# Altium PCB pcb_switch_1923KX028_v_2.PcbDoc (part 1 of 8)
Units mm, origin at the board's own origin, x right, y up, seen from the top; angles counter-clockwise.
Board outline 297.2 x 112.05 mm, 6 copper layers (Component Side, GND Layer 1, Inner Layer 1, Inner Layer 2, GND Layer 2, Solder Side), stack 1.578 mm thick; 545 components, 377 nets, 3174 pads, 1537 vias.
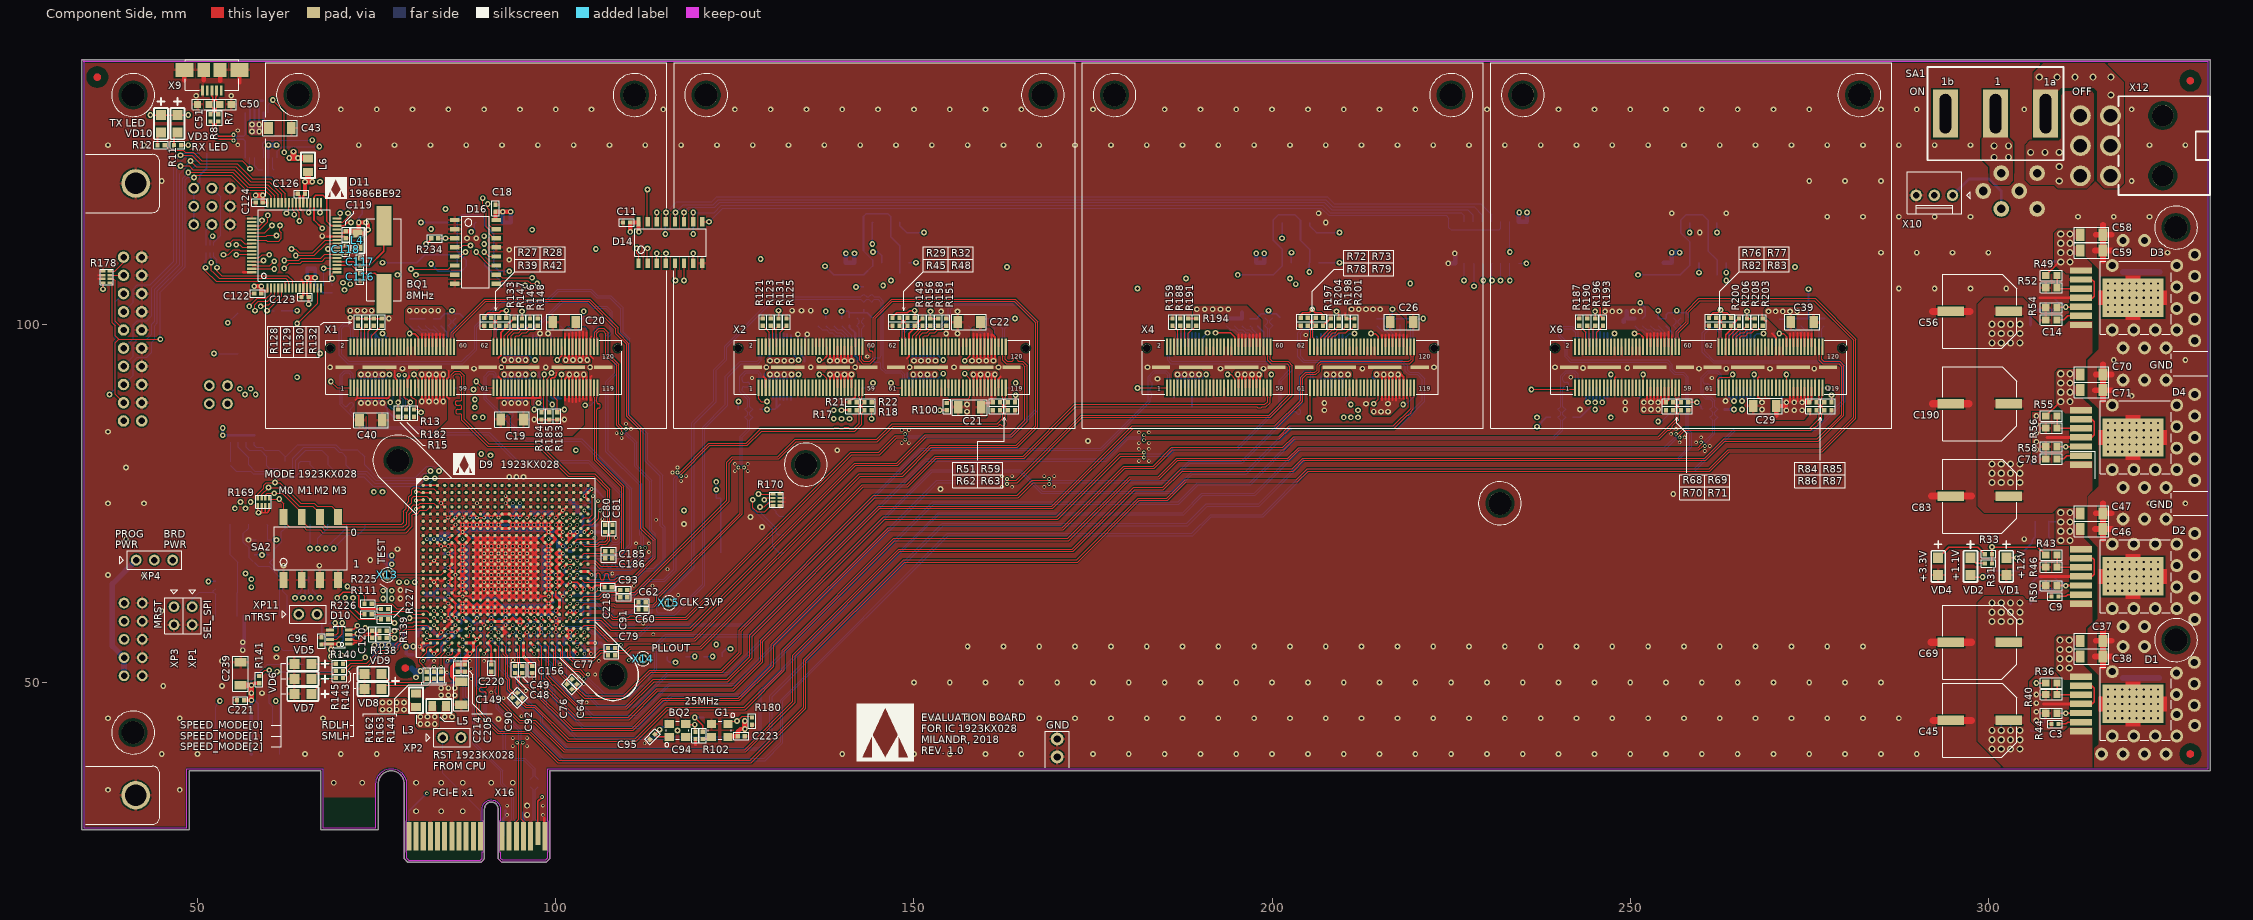
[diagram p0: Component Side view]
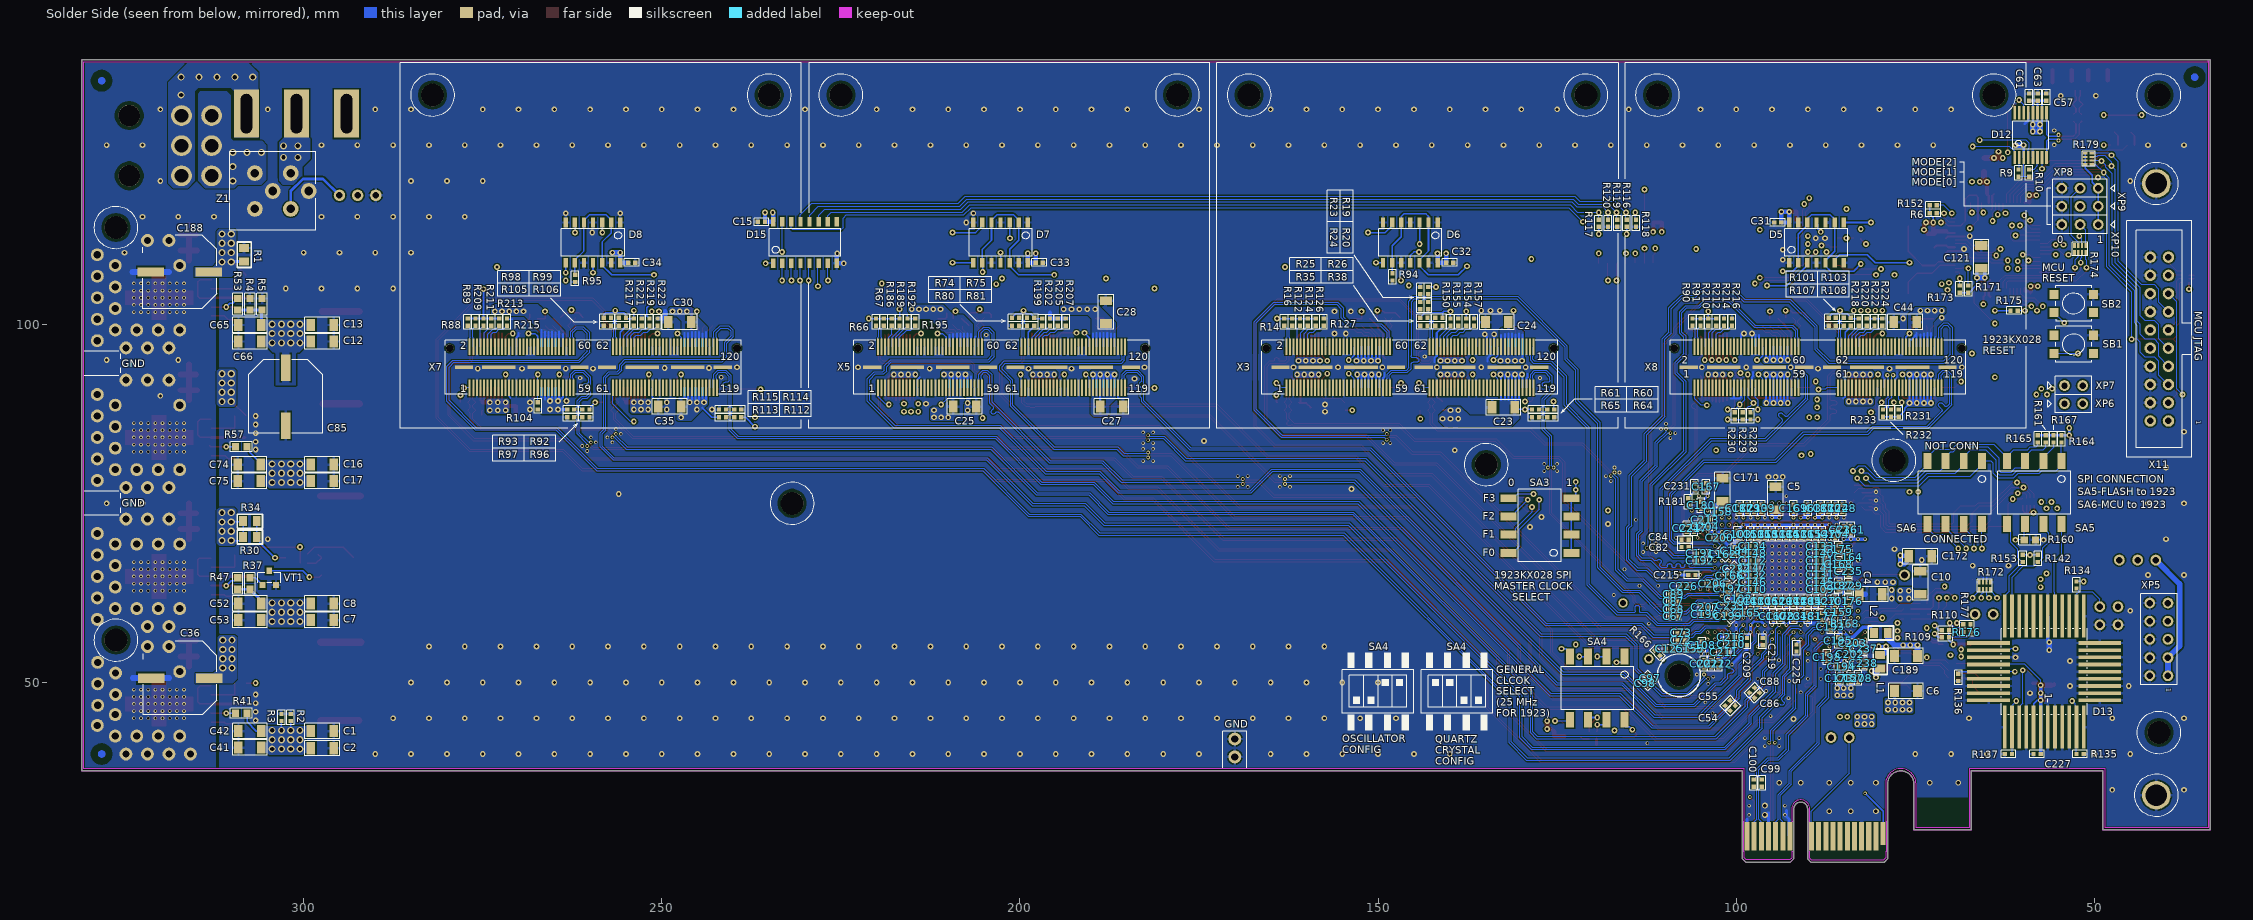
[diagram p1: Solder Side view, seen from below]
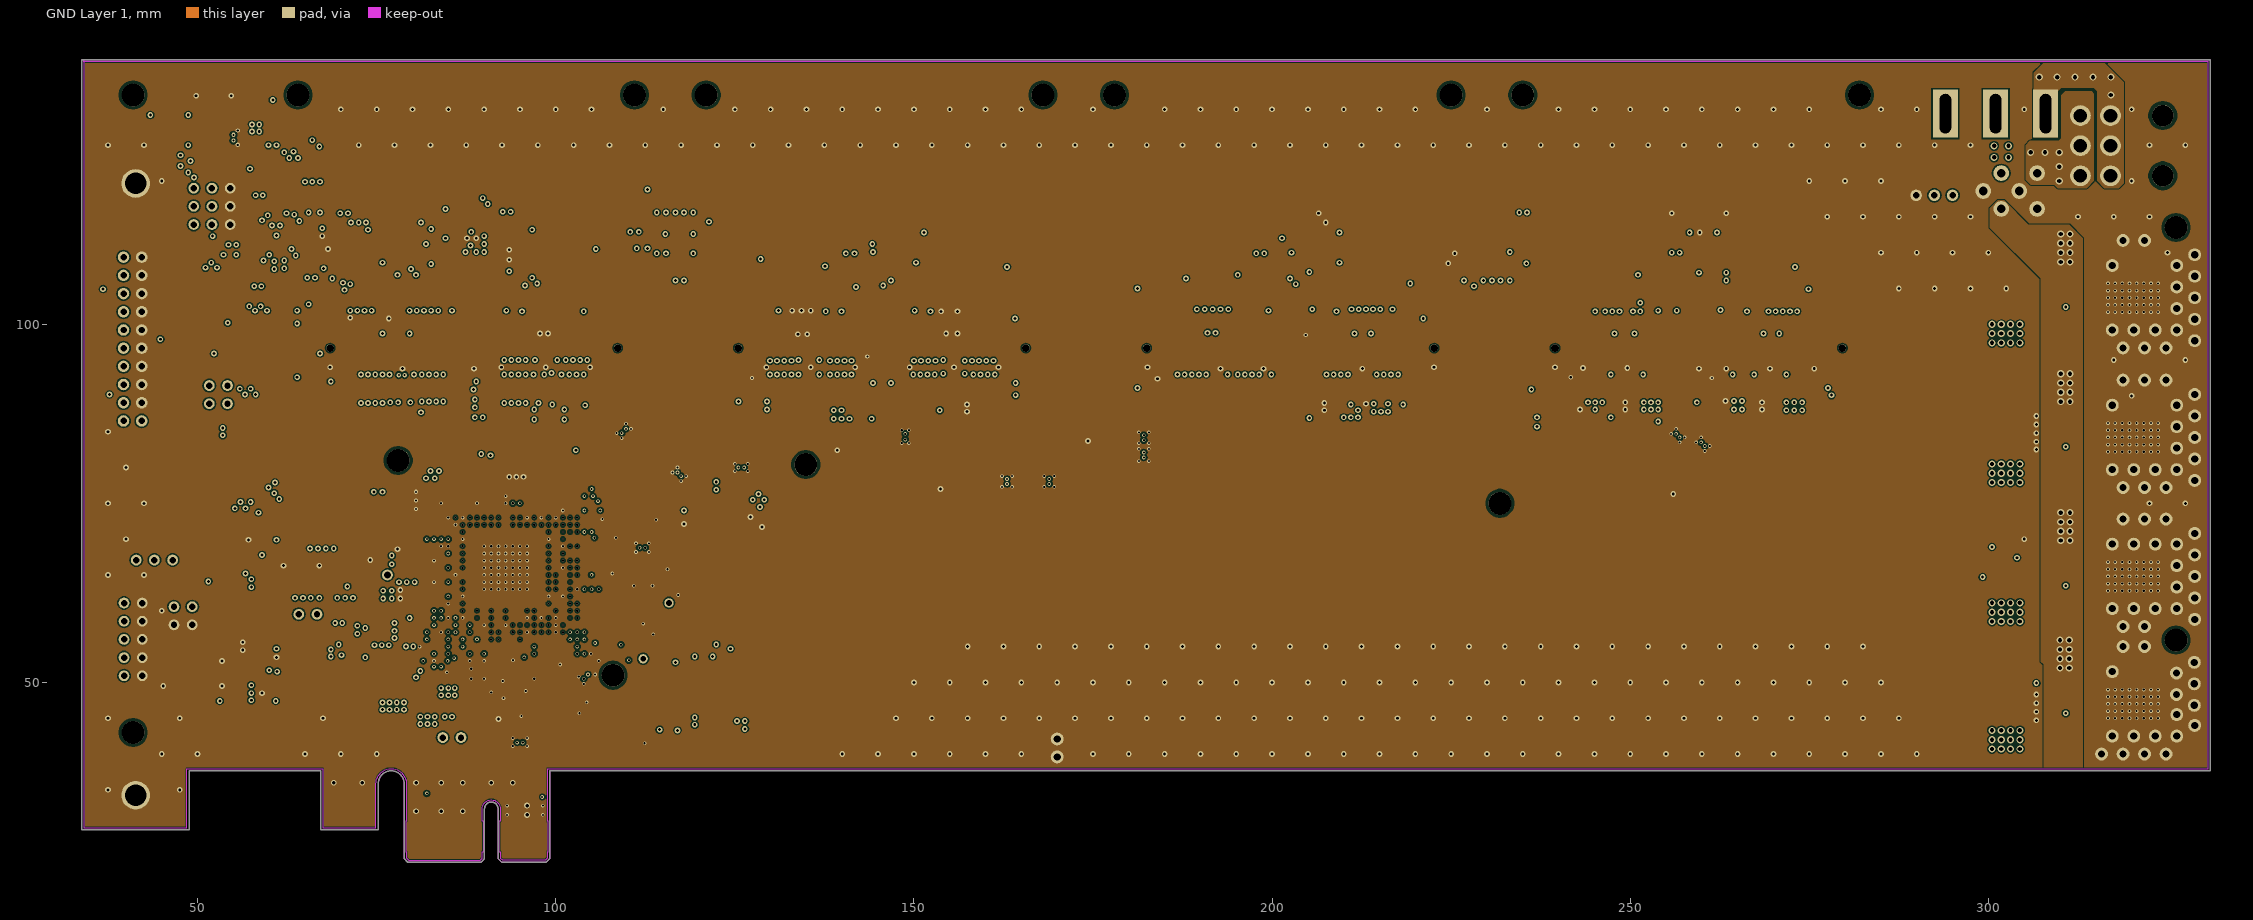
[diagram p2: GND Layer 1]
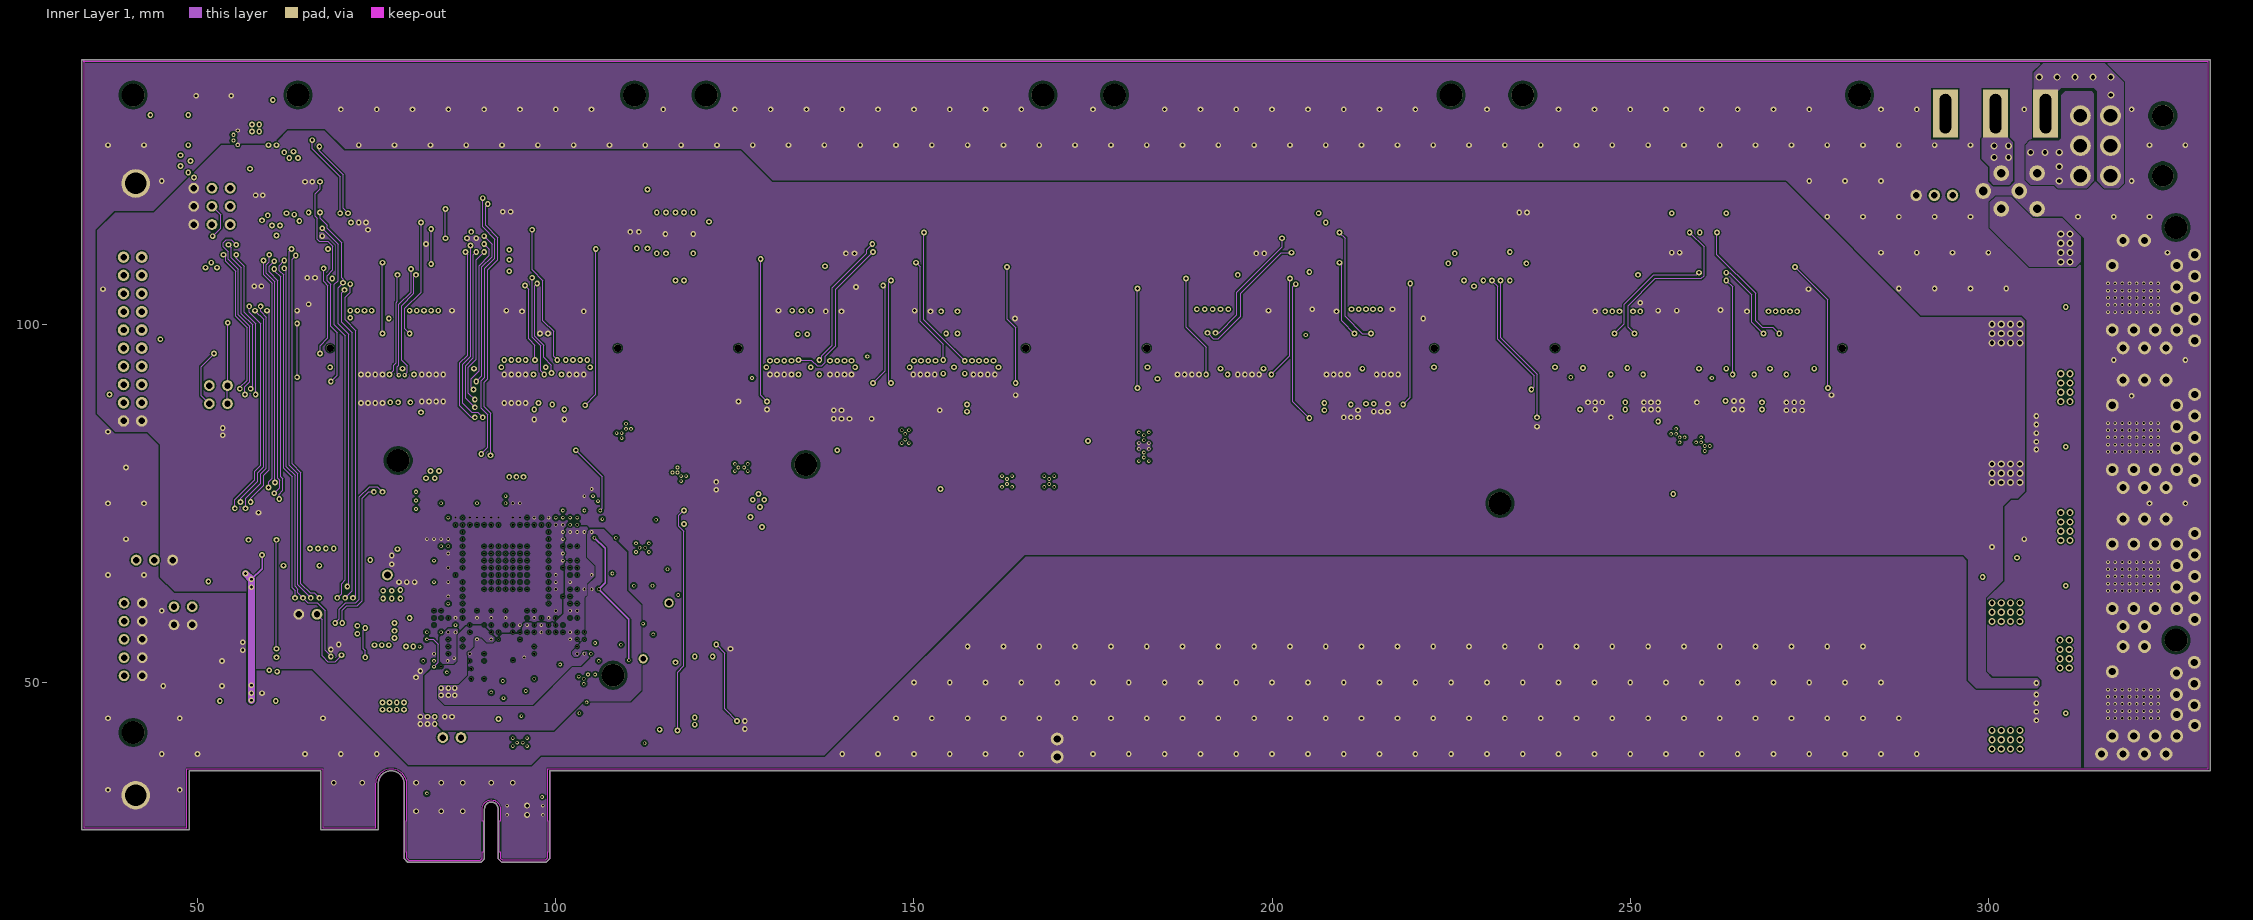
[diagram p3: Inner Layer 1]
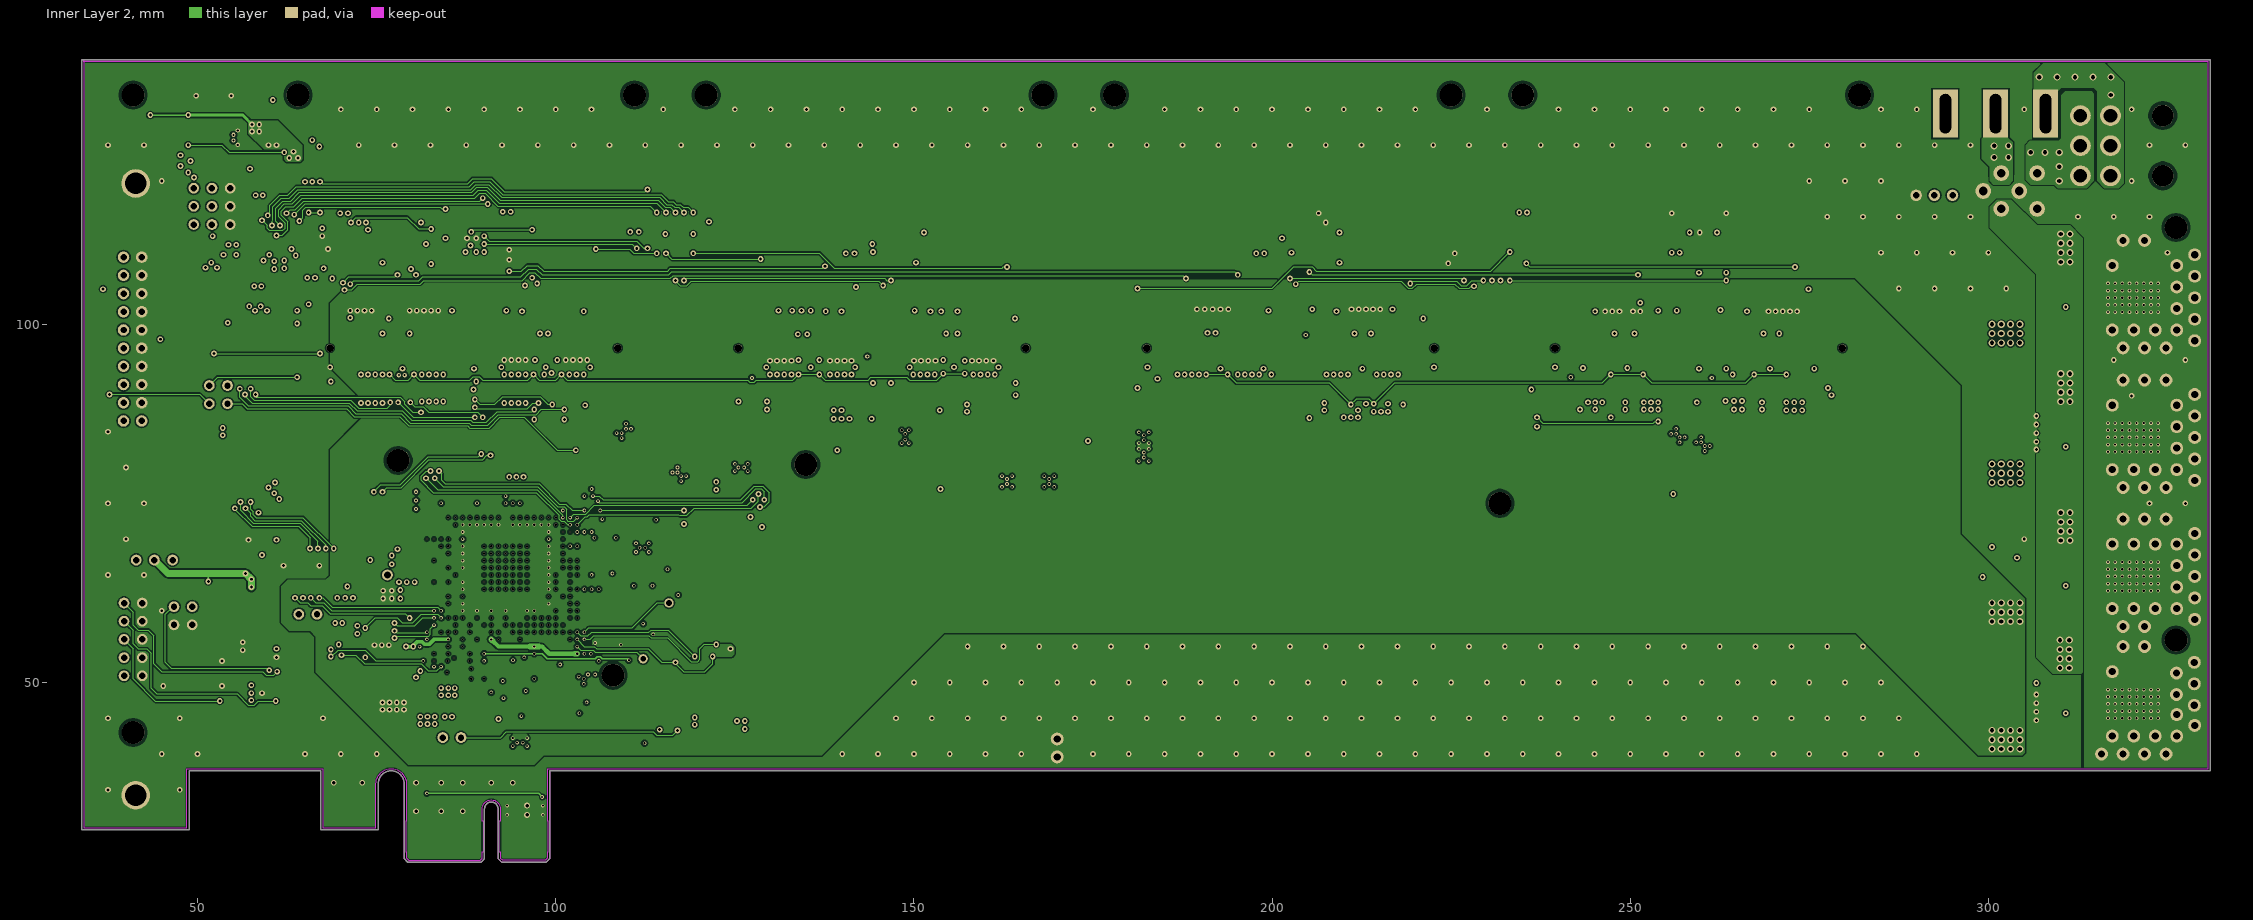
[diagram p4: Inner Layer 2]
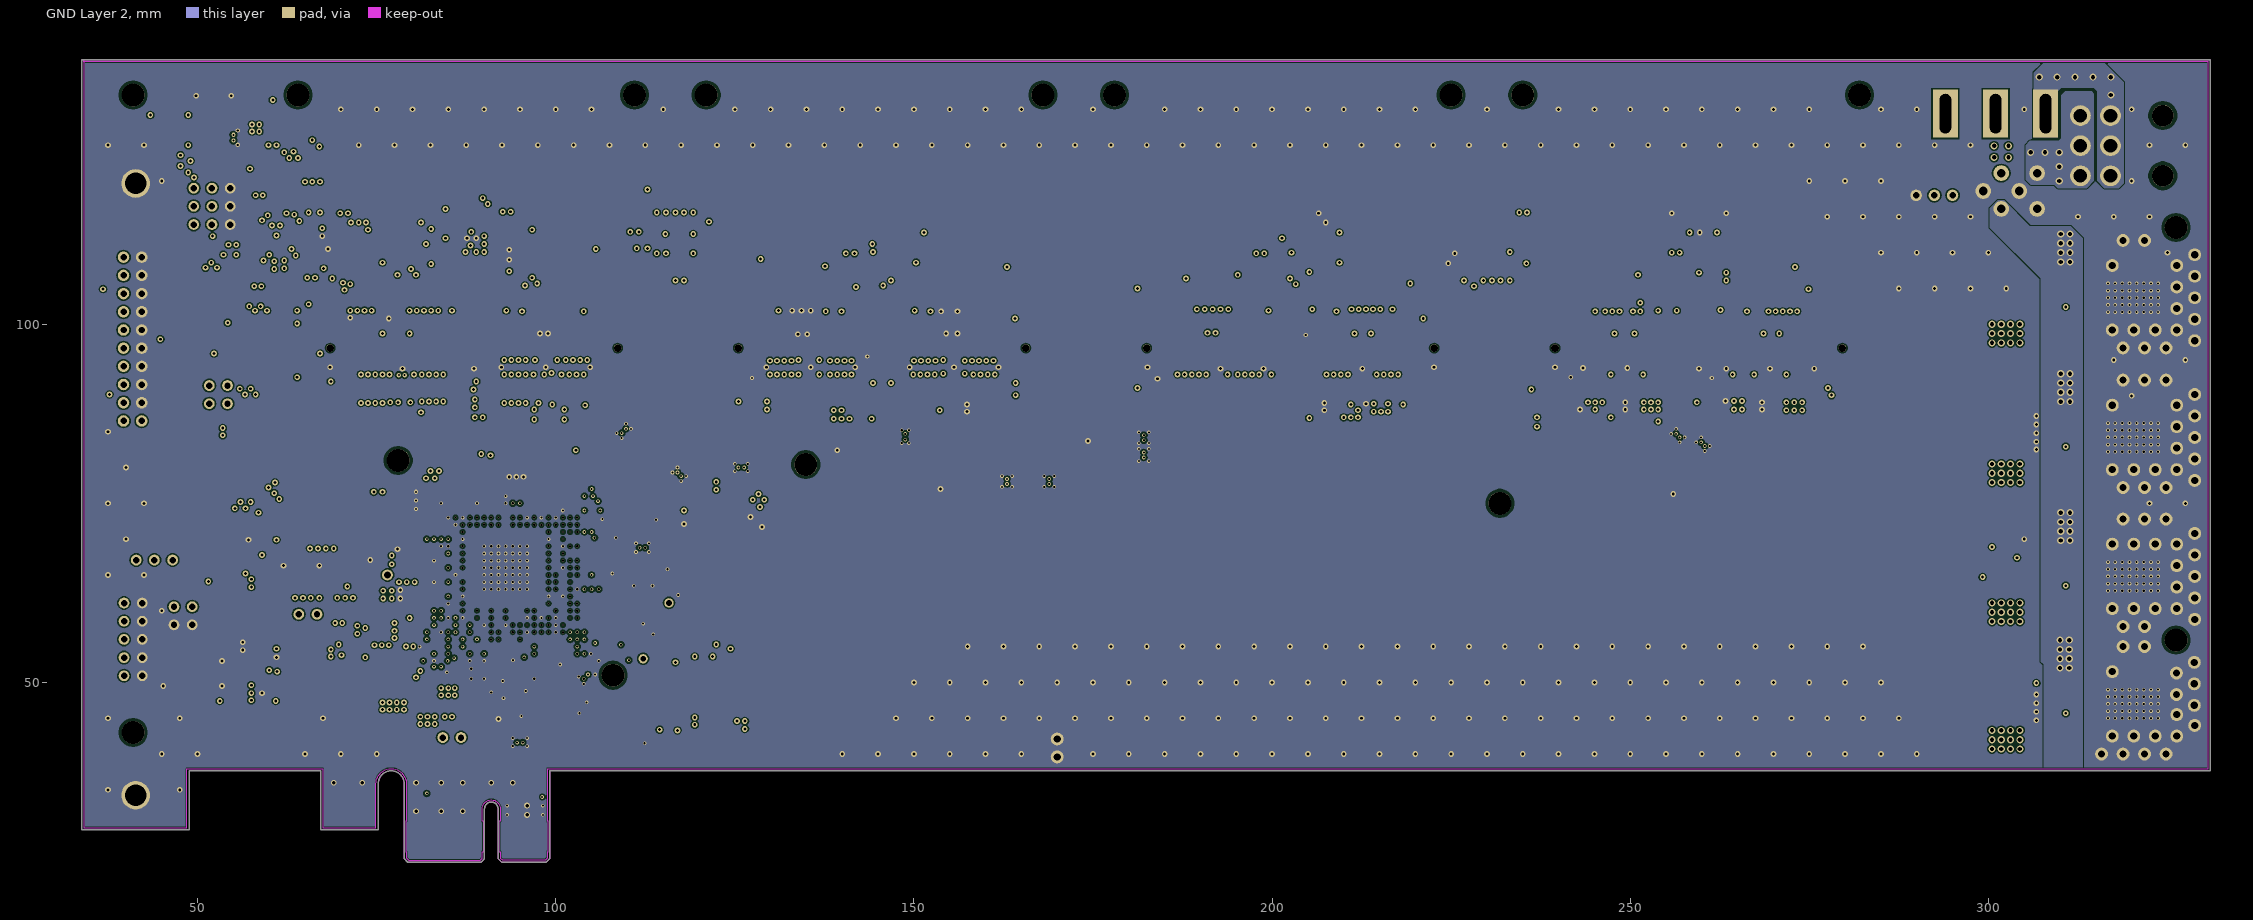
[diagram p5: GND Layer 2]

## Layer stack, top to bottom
Top Solder: solder mask 0.0102, Solder Resist, Dk 3.5
Component Side: signal copper 0.018
Dielectric 1: prepreg 0.15, Prepreg_1080, Dk 4.2
GND Layer 1: signal copper 0.018
Dielectric 3: core 0.51, FR-4, Dk 4.7
Inner Layer 1: signal copper 0.018
Dielectric 6: prepreg 0.15, Prepreg_1080, Dk 4.2
Inner Layer 2: signal copper 0.018
Dielectric 5: core 0.51, FR-4, Dk 4.7
GND Layer 2: signal copper 0.018
Dielectric 4: prepreg 0.15, Prepreg_1080, Dk 4.2
Solder Side: signal copper 0.018
Bottom Solder: solder mask 0.0102, Solder Resist, Dk 3.5

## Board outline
48.8,29.4 48.8,37.65 67.2,37.65 67.2,29.4 75.2,29.4 75.2,35.825 cw(c77.025,35.825) 78.85,35.825 78.85,25.4 79.35,24.9 89.575,24.9 90.05,25.375 90.05,32.35 cw(c91,32.35) 91.95,32.35 91.95,25.4 92.425,24.925 98.675,24.925 99.15,25.4 99.15,37.65 331,37.65 331,136.95 33.8,136.95 33.8,29.4
cut-out: 33.8,136.95 34.1,136.95 34.1,29.7 48.5,29.7 48.5,37.95 67.5,37.95 67.5,29.7 74.9,29.7 74.9,35.825 cw(c77.025,35.825) 79.15,35.825 79.15,30.625 79.025,30.625 79.025,26.375 79.15,26.375 79.15,25.5 79.45,25.2 89.475,25.2 89.75,25.475 89.75,26.375 89.975,26.375 89.975,30.625 89.75,30.625 89.75,32.35 cw(c91,32.35) 92.25,32.35 92.25,30.625 92.025,30.625 92.025,26.375 92.25,26.375 92.25,25.475 92.5,25.225 98.575,25.225 98.85,25.5 98.85,26.375 98.975,26.375 98.975,30.625 98.85,30.625 98.85,37.95 330.7,37.95 330.7,136.65 34.1,136.65 34.1,136.95 331,136.95 331,37.65 99.15,37.65 99.15,25.4 98.675,24.925 92.425,24.925 91.95,25.4 91.95,32.35 ccw(c91,32.35) 90.05,32.35 90.05,25.375 89.575,24.9 79.35,24.9 78.85,25.4 78.85,35.825 ccw(c77.025,35.825) 75.2,35.825 75.2,29.4 67.2,29.4 67.2,37.65 48.8,37.65 48.8,29.4 33.8,29.4

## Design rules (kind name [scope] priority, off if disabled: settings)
Clearance Clearance_On_Internal_LAYER_2_vs_VIA [OnLayer('Inner Layer 2') vs IsVia] p1 off: gap=0.125 except(0.15: Arc-Via Track-Via SMDPad-Via; 0.2: Arc-Poly Track-Poly SMDPad-Fill SMDPad-Poly THPad-Via THPad-Poly Via-Via Fill-Poly Poly-Poly Poly-Region Poly-Text; 0.25: Track-THPad Via-Poly; 0.35: Arc-THPad SMDPad-THPad THPad-THPad THPad-Fill THPad-Region THPad-Text Via-Fill Via-Region Via-Text)
Clearance Clearance_On_Internal_Layer_1_vs_VIA [OnLayer('Inner Layer 1') vs IsVia] p2 off: gap=0.125 except(0.15: Arc-Via Track-Via SMDPad-Via; 0.2: Arc-Poly Track-Poly SMDPad-Fill SMDPad-Poly THPad-Via Via-Via Fill-Poly Poly-Poly Poly-Region Poly-Text; 0.25: Track-THPad THPad-Poly Via-Poly; 0.35: Arc-THPad SMDPad-THPad THPad-THPad THPad-Fill THPad-Region THPad-Text Via-Fill Via-Region Via-Text)
Clearance Clearance_On_BOTTOM_LAYER_vs_VIA [OnLayer('Solder Side') vs IsVia] p3 off: gap=0.125 except(0.15: Arc-Via Track-Via SMDPad-Via; 0.2: Arc-Poly Track-Poly SMDPad-Fill SMDPad-Poly THPad-Via THPad-Poly Via-Via Via-Poly Fill-Poly Poly-Poly Poly-Region Poly-Text; 0.25: Track-THPad; 0.35: Arc-THPad SMDPad-THPad THPad-THPad THPad-Fill THPad-Region THPad-Text Via-Fill Via-Region Via-Text)
Clearance Clearance_On_TOP_LAYER_vs_VIA [OnLayer('Component Side') vs isVia] p4 off: gap=0.125 except(0.15: Arc-Via Track-Via SMDPad-Via; 0.2: Arc-Poly Track-Poly SMDPad-Fill SMDPad-Poly THPad-Via THPad-Poly Via-Via Via-Poly Fill-Poly Poly-Poly Poly-Region Poly-Text; 0.25: Track-THPad; 0.35: Arc-THPad SMDPad-THPad THPad-THPad THPad-Fill THPad-Region THPad-Text Via-Fill Via-Region Via-Text)
Clearance Clearance_Int_layer_1_vs_VIA_without_an_ring [HoleDiameter < 0.4 vs OnLayer('Inner Layer 1')] p5: gap=0.125 except(0.15: Arc-Via Track-Via SMDPad-Via; 0.2: Arc-Poly Track-Poly SMDPad-Fill SMDPad-Poly THPad-Via THPad-Poly Via-Via Fill-Poly Poly-Poly Poly-Region Poly-Text; 0.25: Track-THPad Via-Fill Via-Poly Via-Region; 0.35: Arc-THPad SMDPad-THPad THPad-THPad THPad-Fill THPad-Region THPad-Text Via-Text)
Clearance Clearance_Int_layer_2_vs_VIA_without_an_ring [HoleDiameter < 0.4 vs OnLayer('Inner Layer 2')] p6: gap=0.125 except(0.15: Arc-Via Track-Via SMDPad-Via; 0.2: Arc-Poly Track-Poly SMDPad-Fill SMDPad-Poly THPad-Via THPad-Poly Via-Via Fill-Poly Poly-Poly Poly-Region Poly-Text; 0.25: Track-THPad Via-Fill Via-Poly Via-Region; 0.35: Arc-THPad SMDPad-THPad THPad-THPad THPad-Fill THPad-Region THPad-Text Via-Text)
Clearance Clearance_Int_layer_3_vs_VIA_without_an_ring_1 [HoleDiameter < 0.4 vs OnLayer('GND Layer 1')] p7: gap=0.125 except(0.15: Arc-Via Track-Via SMDPad-Via; 0.2: Arc-Poly Track-Poly SMDPad-Fill SMDPad-Poly THPad-Via THPad-Poly Via-Via Fill-Poly Poly-Poly Poly-Region Poly-Text; 0.25: Track-THPad Via-Fill Via-Poly Via-Region; 0.35: Arc-THPad SMDPad-THPad THPad-THPad THPad-Fill THPad-Region THPad-Text Via-Text)
Clearance Clearance_Int_layer_4_vs_VIA_without_an_ring [HoleDiameter < 0.4 vs OnLayer('GND Layer 2')] p8: gap=0.125 except(0.15: Arc-Via Track-Via SMDPad-Via; 0.2: Arc-Poly Track-Poly SMDPad-Fill SMDPad-Poly THPad-Via THPad-Poly Via-Via Fill-Poly Poly-Poly Poly-Region Poly-Text; 0.25: Track-THPad Via-Fill Via-Poly Via-Region; 0.35: Arc-THPad SMDPad-THPad THPad-THPad THPad-Fill THPad-Region THPad-Text Via-Text)
Clearance [All] p9: gap=0.125 except(0.15: Arc-Via Track-Via SMDPad-Via; 0.17: Via-Poly; 0.2: Arc-Poly Track-Poly SMDPad-Fill SMDPad-Poly THPad-Via THPad-Poly Via-Via Fill-Poly Poly-Poly Poly-Region Poly-Text; 0.25: Track-THPad; 0.35: Arc-THPad SMDPad-THPad THPad-THPad THPad-Fill THPad-Region THPad-Text Via-Fill Via-Region Via-Text)
ComponentClearance [All] p1 off: gap=0.01 collisioncheckmode=3 verticalgap=0.01 showdistances=FALSE
ComponentOrientations [All] p1: allowedrotations=32
DiffPairsRouting "Schematic Differential Pairs Routing_3" [InNet('USB_D_P')] p1: maxlimit=0.3 minlimit=0.125 mostfreqgap=0.254 toplayer_prefgap=0.21 toplayer_minwidth=0.125 toplayer_maxwidth=0.3 toplayer_prefwidth=0.22 midlayer1_mingap=0.254 midlayer1_maxgap=0.254 midlayer1_minwidth=0.381 midlayer1_maxwidth=0.381 midlayer1_prefwidth=0.381 midlayer2_mingap=0.254 midlayer2_maxgap=0.254 midlayer2_minwidth=0.381 midlayer2_maxwidth=0.381 midlayer2_prefwidth=0.381 midlayer3_mingap=0.254 midlayer3_maxgap=0.254 midlayer3_minwidth=0.381 midlayer3_maxwidth=0.381 midlayer3_prefwidth=0.381 midlayer4_mingap=0.254 midlayer4_maxgap=0.254 midlayer4_minwidth=0.381 midlayer4_maxwidth=0.381 midlayer4_prefwidth=0.381 bottomlayer_prefgap=0.21 bottomlayer_minwidth=0.125 bottomlayer_maxwidth=0.3 bottomlayer_prefwidth=0.22 maxuncoupledlength=12.7
DiffPairsRouting "Schematic Differential Pairs Routing_2" [InNet('USB_D_N')] p2: maxlimit=0.3 minlimit=0.125 mostfreqgap=0.254 toplayer_prefgap=0.21 toplayer_minwidth=0.125 toplayer_maxwidth=0.3 toplayer_prefwidth=0.22 midlayer1_mingap=0.254 midlayer1_maxgap=0.254 midlayer1_minwidth=0.381 midlayer1_maxwidth=0.381 midlayer1_prefwidth=0.381 midlayer2_mingap=0.254 midlayer2_maxgap=0.254 midlayer2_minwidth=0.381 midlayer2_maxwidth=0.381 midlayer2_prefwidth=0.381 midlayer3_mingap=0.254 midlayer3_maxgap=0.254 midlayer3_minwidth=0.381 midlayer3_maxwidth=0.381 midlayer3_prefwidth=0.381 midlayer4_mingap=0.254 midlayer4_maxgap=0.254 midlayer4_minwidth=0.381 midlayer4_maxwidth=0.381 midlayer4_prefwidth=0.381 bottomlayer_prefgap=0.21 bottomlayer_minwidth=0.125 bottomlayer_maxwidth=0.3 bottomlayer_prefwidth=0.22 maxuncoupledlength=12.7
DiffPairsRouting "Schematic Differential Pairs Routing_1" [InNet('_USB_D_P')] p3: maxlimit=0.3 minlimit=0.125 mostfreqgap=0.254 toplayer_prefgap=0.21 toplayer_minwidth=0.125 toplayer_maxwidth=0.3 toplayer_prefwidth=0.22 midlayer1_mingap=0.254 midlayer1_maxgap=0.254 midlayer1_minwidth=0.381 midlayer1_maxwidth=0.381 midlayer1_prefwidth=0.381 midlayer2_mingap=0.254 midlayer2_maxgap=0.254 midlayer2_minwidth=0.381 midlayer2_maxwidth=0.381 midlayer2_prefwidth=0.381 midlayer3_mingap=0.254 midlayer3_maxgap=0.254 midlayer3_minwidth=0.381 midlayer3_maxwidth=0.381 midlayer3_prefwidth=0.381 midlayer4_mingap=0.254 midlayer4_maxgap=0.254 midlayer4_minwidth=0.381 midlayer4_maxwidth=0.381 midlayer4_prefwidth=0.381 bottomlayer_prefgap=0.21 bottomlayer_minwidth=0.125 bottomlayer_maxwidth=0.3 bottomlayer_prefwidth=0.22 maxuncoupledlength=12.7
DiffPairsRouting "Schematic Differential Pairs Routing" [InNet('_USB_D_N')] p4: maxlimit=0.3 minlimit=0.125 mostfreqgap=0.254 toplayer_prefgap=0.21 toplayer_minwidth=0.125 toplayer_maxwidth=0.3 toplayer_prefwidth=0.22 midlayer1_mingap=0.254 midlayer1_maxgap=0.254 midlayer1_minwidth=0.381 midlayer1_maxwidth=0.381 midlayer1_prefwidth=0.381 midlayer2_mingap=0.254 midlayer2_maxgap=0.254 midlayer2_minwidth=0.381 midlayer2_maxwidth=0.381 midlayer2_prefwidth=0.381 midlayer3_mingap=0.254 midlayer3_maxgap=0.254 midlayer3_minwidth=0.381 midlayer3_maxwidth=0.381 midlayer3_prefwidth=0.381 midlayer4_mingap=0.254 midlayer4_maxgap=0.254 midlayer4_minwidth=0.381 midlayer4_maxwidth=0.381 midlayer4_prefwidth=0.381 bottomlayer_prefgap=0.21 bottomlayer_minwidth=0.125 bottomlayer_maxwidth=0.3 bottomlayer_prefwidth=0.22 maxuncoupledlength=12.7
DiffPairsRouting DiffPairsRouting_1 [InDifferentialPairClass('All Differential Pairs')] p5: maxlimit=0.3 minlimit=0.125 mostfreqgap=0.3 toplayer_maxgap=0.2 toplayer_prefgap=0.16 toplayer_minwidth=0.125 toplayer_maxwidth=0.22 toplayer_prefwidth=0.15 midlayer1_minwidth=0.125 midlayer1_maxwidth=0.22 midlayer1_prefwidth=0.15 midlayer2_minwidth=0.125 midlayer2_maxwidth=0.22 midlayer2_prefwidth=0.15 midlayer3_mingap=0.254 midlayer3_maxgap=0.2 midlayer3_prefgap=0.254 midlayer3_minwidth=0.381 midlayer3_maxwidth=0.22 midlayer3_prefwidth=0.381 midlayer4_mingap=0.254 midlayer4_maxgap=0.2 midlayer4_prefgap=0.254 midlayer4_minwidth=0.381 midlayer4_maxwidth=0.22 midlayer4_prefwidth=0.381 bottomlayer_maxgap=0.2 bottomlayer_prefgap=0.16 bottomlayer_minwidth=0.125 bottomlayer_maxwidth=0.22 bottomlayer_prefwidth=0.15 maxuncoupledlength=20
Height [All] p1 off: minheight=0 maxheight=50 prefheight=25
HoleSize [All] p1: absolutevalues=TRUE maxlimit=6 minlimit=0.3 maxpercent=80.000 minpercent=20.000
HoleToHoleClearance [All] p1: gap=0.2 allowstackedmicrovias=FALSE
MinimumSolderMaskSliver [All] p1: minsoldermaskwidth=0.01
PlaneClearance [All] p1: clearance=0.35
PlaneConnect PlaneConnect_2 [InNet('+12') Or InNet('NetXP3_4')] p1 off: planeconnectstyle=Direct reliefexpansion=0.508 reliefentries=4 reliefconductorwidth=0.254 reliefairgap=0.254
PlaneConnect [IsVia] p2: planeconnectstyle=Direct reliefexpansion=0.508 reliefentries=4 reliefconductorwidth=0.254 reliefairgap=0.254
PlaneConnect PlaneConnect_1 [All] p3: planeconnectstyle=Relief reliefexpansion=0.1 reliefentries=4 reliefconductorwidth=0.2 reliefairgap=0.2
PolygonConnect connection_poly_by_name [All vs IsNamedPolygon('TL_USB_3.3V') Or IsNamedPolygon('IL2_USB_3.3V') Or IsNamedPolygon('IL2_NetSA1_2') Or IsNamedPolygon('TL_NetXP3_4') Or IsNamedPolygon('IL2_12V') Or IsNamedPolygon('CS_GND_DIRECT_CONN') Or IsNamedPolygon('TL_DIRTY_GND') Or IsNamedPolygon('TL_1.1V') Or IsNamedPolygon('TL_3.3V') or IsNamedPolygon('TL_NET_FIL_3.3V') or IsNamedPolygon('TL_D9_1.1V') Or IsNamedPolygon('TL_D9_1.1V_PCIE') Or IsNamedPolygon('ALL_+1.1') Or IsNamedPolygon('ALL_+3.3') Or IsNamedPolygon('Inner_Layer_1_INPUTPWR') oR IsNamedPolygon('IL1_GND') Or IsNamedPolygon('BL_1.1_X5') or IsNamedPolygon('TL_GND_X') Or IsNamedPolygon('BL_3.3_X3') Or IsNamedPolygon('INT_LAYER_GND')] p1: connectstyle=Direct reliefconductorwidth=0.254 reliefentries=4 polygonreliefangle="90 Angle" airgapwidth=0.254
PolygonConnect connection_via [IsVia] p2: connectstyle=Direct reliefconductorwidth=0.254 reliefentries=4 polygonreliefangle="90 Angle" airgapwidth=0.254
PolygonConnect connection_QSH_central_pads [HasFootprint('QSH-60-01-F-D-A')] p3: connectstyle=Relief reliefconductorwidth=0.28 reliefentries=4 polygonreliefangle="90 Angle" airgapwidth=0.2
PolygonConnect connection_1923 [HasFootprint('FOOTPRINT_MK8303.576-1')] p4: connectstyle=Relief reliefconductorwidth=0.2 reliefentries=4 polygonreliefangle="45 Angle" airgapwidth=0.2
PolygonConnect connection_all [All] p5: connectstyle=Relief reliefconductorwidth=0.4 reliefentries=4 polygonreliefangle="90 Angle" airgapwidth=0.2
RoutingCorners RoutingCorners_1 [All] p1: cornerstyle=45-Degree minsetback=2.54 maxsetback=2.54
RoutingLayers RoutingLayers_1 [All] p1: top layer_v5=TRUE mid layer 1_v5=TRUE mid layer 2_v5=TRUE mid layer 3_v5=TRUE mid layer 4_v5=TRUE bottom layer_v5=TRUE
RoutingLayers RoutingLayers_for_Diff [InDifferentialPairClass('All Differential Pairs')] p2 off: top layer_v5=FALSE mid layer 1_v5=FALSE mid layer 2_v5=FALSE mid layer 3_v5=TRUE mid layer 4_v5=TRUE bottom layer_v5=FALSE
RoutingVias [All] p1: holewidth=0.3 width=0.5 viastyle="Through Hole" minholewidth=0.3 minwidth=0.3 maxholewidth=0.6 maxwidth=1
SilkToSilkClearance [All] p1: silktosilkclearance=0.01
SilkToSolderMaskClearance [IsPad] p1: minsilkscreentomaskgap=0.01 clearancetoexposedcopper=TRUE
SolderMaskExpansion [All] p1: expansion=0.05
Width [All] p1: maxlimit=1 minlimit=0.125 preferedwidth=0.15
18 further rules are at their usual default settings.

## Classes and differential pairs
differential pair USB_D: +USB_D_P -USB_D_N
differential pair SGMII_L3DATO_3: +SGMII_L3DATO_3_P -SGMII_L3DATO_3_N
differential pair SGMII_L3DATO_2: +SGMII_L3DATO_2_P -SGMII_L3DATO_2_N
differential pair SGMII_L3DATO_1: +SGMII_L3DATO_1_P -SGMII_L3DATO_1_N
differential pair SGMII_L3DATO_0: +SGMII_L3DATO_0_P -SGMII_L3DATO_0_N
differential pair SGMII_L3DATI_3: +SGMII_L3DATI_3_P -SGMII_L3DATI_3_N
differential pair SGMII_L3DATI_2: +SGMII_L3DATI_2_P -SGMII_L3DATI_2_N
differential pair SGMII_L3DATI_1: +SGMII_L3DATI_1_P -SGMII_L3DATI_1_N
differential pair SGMII_L3DATI_0: +SGMII_L3DATI_0_P -SGMII_L3DATI_0_N
differential pair SGMII_L2DATO_3: +SGMII_L2DATO_3_P -SGMII_L2DATO_3_N
differential pair SGMII_L2DATO_2: +SGMII_L2DATO_2_P -SGMII_L2DATO_2_N
differential pair SGMII_L2DATO_1: +SGMII_L2DATO_1_P -SGMII_L2DATO_1_N
differential pair SGMII_L2DATO_0: +SGMII_L2DATO_0_P -SGMII_L2DATO_0_N
differential pair SGMII_L2DATI_3: +SGMII_L2DATI_3_P -SGMII_L2DATI_3_N
differential pair SGMII_L2DATI_2: +SGMII_L2DATI_2_P -SGMII_L2DATI_2_N
differential pair SGMII_L2DATI_1: +SGMII_L2DATI_1_P -SGMII_L2DATI_1_N
differential pair SGMII_L2DATI_0: +SGMII_L2DATI_0_P -SGMII_L2DATI_0_N
differential pair SGMII_L1DATO_3: +SGMII_L1DATO_3_P -SGMII_L1DATO_3_N
differential pair SGMII_L1DATO_2: +SGMII_L1DATO_2_P -SGMII_L1DATO_2_N
differential pair SGMII_L1DATO_1: +SGMII_L1DATO_1_P -SGMII_L1DATO_1_N
differential pair SGMII_L1DATO_0: +SGMII_L1DATO_0_P -SGMII_L1DATO_0_N
differential pair SGMII_L1DATI_3: +SGMII_L1DATI_3_P -SGMII_L1DATI_3_N
differential pair SGMII_L1DATI_2: +SGMII_L1DATI_2_P -SGMII_L1DATI_2_N
differential pair SGMII_L1DATI_1: +SGMII_L1DATI_1_P -SGMII_L1DATI_1_N
differential pair SGMII_L1DATI_0: +SGMII_L1DATI_0_P -SGMII_L1DATI_0_N
differential pair SGMII_L0DATO_1: +SGMII_L0DATO_1_P -SGMII_L0DATO_1_N
differential pair SGMII_L0DATO_0: +SGMII_L0DATO_0_P -SGMII_L0DATO_0_N
differential pair SGMII_L0DATI_1: +SGMII_L0DATI_1_P -SGMII_L0DATI_1_N
differential pair SGMII_L0DATI_0: +SGMII_L0DATI_0_P -SGMII_L0DATI_0_N
differential pair _USB_D: +_USB_D_P -_USB_D_N
differential pair _SGMII_L3DATI_3: +M_SGMII_L3DATI_3_P -M_SGMII_L3DATI_3_N
differential pair _SGMII_L3DATI_2: +M_SGMII_L3DATI_2_P -M_SGMII_L3DATI_2_N
differential pair _SGMII_L3DATI_1: +M_SGMII_L3DATI_1_P -M_SGMII_L3DATI_1_N
differential pair _SGMII_L3DATI_0: +M_SGMII_L3DATI_0_P -M_SGMII_L3DATI_0_N
differential pair _SGMII_L2DATI_3: +M_SGMII_L2DATI_3_P -M_SGMII_L2DATI_3_N
differential pair _SGMII_L2DATI_2: +M_SGMII_L2DATI_2_P -M_SGMII_L2DATI_2_N
differential pair _SGMII_L2DATI_1: +M_SGMII_L2DATI_1_P -M_SGMII_L2DATI_1_N
differential pair _SGMII_L2DATI_0: +M_SGMII_L2DATI_0_P -M_SGMII_L2DATI_0_N
differential pair _SGMII_L1DATI_3: +M_SGMII_L1DATI_3_P -M_SGMII_L1DATI_3_N
differential pair _SGMII_L1DATI_2: +M_SGMII_L1DATI_2_P -M_SGMII_L1DATI_2_N
differential pair _SGMII_L1DATI_1: +M_SGMII_L1DATI_1_P -M_SGMII_L1DATI_1_N
differential pair _SGMII_L1DATI_0: +M_SGMII_L1DATI_0_P -M_SGMII_L1DATI_0_N
differential pair _SGMII_L0DATI_3: +M_SGMII_L0DATI_3_P -M_SGMII_L0DATI_3_N
differential pair _SGMII_L0DATI_2: +M_SGMII_L0DATI_2_P -M_SGMII_L0DATI_2_N
differential pair _SGMII_L0DATI_1: +M_SGMII_L0DATI_1_P -M_SGMII_L0DATI_1_N
differential pair _SGMII_L0DATI_0: +M_SGMII_L0DATI_0_P -M_SGMII_L0DATI_0_N
differential pair PCI_E_TX: +PCI_E_TX_P -PCI_E_TX_N
differential pair PCI_E_RX: +PCI_E_RX_P -PCI_E_RX_N
differential pair PCI_E_CLK: +PCI_E_CLK_P -PCI_E_CLK_N
differential pair NET_TMP_DX: +NET_TMP_DX_P -NET_TMP_DX_N
differential pair NET_DX: +NET_DX_P -NET_DX_N
differential pair CAP_PCI_E_TX: +CAP_PCI_E_TX_P -CAP_PCI_E_TX_N
differential pair SGMII_L0DATI_2: +SGMII_L0DATI_2_P -SGMII_L0DATI_2_N
differential pair SGMII_L0DATI_3: +SGMII_L0DATI_3_P -SGMII_L0DATI_3_N
differential pair SGMII_L0DATO_2: +SGMII_L0DATO_2_P -SGMII_L0DATO_2_N
differential pair SGMII_L0DATO_3: +SGMII_L0DATO_3_P -SGMII_L0DATO_3_N

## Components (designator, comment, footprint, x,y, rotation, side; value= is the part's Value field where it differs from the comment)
BQ1 "8MHz, HS49SM" HS49SM 76,109 r90 top
BQ2 "25.0MHz, 30ppm, CL = 12pF, KX-7" FOOTPRINT_KX7 117,43.3 r0 top locked
C1 "100uF, X5R, 6.3В, 1206" FOOTPRINT_1206#1 297.4,43.2 r180 bottom
C2 "100uF, X5R, 6.3В, 1206" FOOTPRINT_1206#1 297.4,40.8 r180 bottom
C3 "100nF, 10V, X5R, 0402" FOOTPRINT_0402 309.3,44.2 r180 top
C4 "100uF, X5R, 6.3В, 1206" FOOTPRINT_1206#1 81.2,62.3 r180 bottom
C5 "100uF, X5R, 6.3В, 1206" FOOTPRINT_1206#1 94.5,75.7 r90 bottom
C6 "100uF, X5R, 6.3В, 1206" FOOTPRINT_1206#1 76.3,48.8 r180 bottom
C7 "100uF, X5R, 6.3В, 1206" FOOTPRINT_1206#1 297.4,58.7 r180 bottom
C8 "100uF, X5R, 6.3В, 1206" FOOTPRINT_1206#1 297.4,61 r180 bottom
C9 "100nF, 10V, X5R, 0402" FOOTPRINT_0402 309.3,62 r180 top
C10 "100uF, X5R, 6.3В, 1206" FOOTPRINT_1206#1 74.3,63.9 r90 bottom
C11 "100nF, 10V, X5R, 0402" FOOTPRINT_0402 109.9,114.2 r180 top
C12 "100uF, X5R, 6.3В, 1206" FOOTPRINT_1206#1 297.4,97.6 r180 bottom
C13 "100uF, X5R, 6.3В, 1206" FOOTPRINT_1206#1 297.4,99.9 r180 bottom
C14 "470nF, X7R, 16V, 10%, 0603" FOOTPRINT_0603 308.8,100.6 r180 top
C15 "100nF, 10V, X5R, 0402" FOOTPRINT_0402 236.1,114.3 r0 bottom
C16 "100uF, X5R, 6.3В, 1206" FOOTPRINT_1206#1 297.4,80.4 r180 bottom
C17 "100uF, X5R, 6.3В, 1206" FOOTPRINT_1206#1 297.4,78.1 r180 bottom
C18 "100nF, 10V, X5R, 0402" FOOTPRINT_0402 91.6,116.2 r270 top
C19 "100uF, X5R, 6.3В, 1206" FOOTPRINT_1206#1 93.9,86.7 r180 top
C20 "100uF, X5R, 6.3В, 1206" FOOTPRINT_1206#1 101.2,100.3 r180 top
C21 "100uF, X5R, 6.3В, 1206" FOOTPRINT_1206#1 157.8,88.4 r180 top
C22 "100uF, X5R, 6.3В, 1206" FOOTPRINT_1206#1 157.7,100.3 r180 top
C23 "100uF, X5R, 6.3В, 1206" FOOTPRINT_1206#2 132.5,88.4 r0 bottom
C24 "100uF, X5R, 6.3В, 1206" FOOTPRINT_1206#1 133.4,100.3 r0 bottom
C25 "100uF, X5R, 6.3В, 1206" FOOTPRINT_1206#1 207.7,88.5 r180 bottom
C26 "100uF, X5R, 6.3В, 1206" FOOTPRINT_1206#1 218.1,100.3 r0 top
C27 "100uF, X5R, 6.3В, 1206" FOOTPRINT_1206#1 187.2,88.5 r180 bottom
C28 "100uF, X5R, 6.3В, 1206" FOOTPRINT_1206#1 188,101.7 r90 bottom
C29 "100uF, X5R, 6.3В, 1206" FOOTPRINT_1206#1 268.8,88.6 r180 top
C30 "100uF, X5R, 6.3В, 1206" FOOTPRINT_1206#1 247.5,100.3 r0 bottom
C31 "100nF, 10V, X5R, 0402" FOOTPRINT_0402 94.2,114.2 r180 bottom
C32 "100nF, 10V, X5R, 0402" FOOTPRINT_0402 140,108.6 r0 bottom
C33 "100nF, 10V, X5R, 0402" FOOTPRINT_0402 197.3,108.6 r0 bottom
C34 "100nF, 10V, X5R, 0402" FOOTPRINT_0402 254.2,108.6 r0 bottom
C35 "100uF, X5R, 6.3В, 1206" FOOTPRINT_1206#1 248.9,88.5 r0 bottom
C36 "470uF, 16V, SMD, 10.3 x 10.3" FOOTPRINT_SVPE_F12 317.25,50.6 r90 bottom
C37 "10 uF, 10%, 25V, X5R, 1206" FOOTPRINT_1206#1 314.4,55.8 r0 top
C38 "10 uF, 10%, 25V, X5R, 1206" FOOTPRINT_1206#1 314.4,53.6 r0 top
C39 "100uF, X5R, 6.3В, 1206" FOOTPRINT_1206#1 274,100.3 r0 top
C40 "100uF, X5R, 6.3В, 1206" FOOTPRINT_1206#1 74.2,86.6 r180 top
C41 "10 uF, 10%, 25V, X5R, 1206" FOOTPRINT_1206#1 307.5,40.9 r0 bottom
C42 "10 uF, 10%, 25V, X5R, 1206" FOOTPRINT_1206#1 307.5,43.2 r0 bottom
C43 "10 uF, 10%, 25V, X5R, 1206" FOOTPRINT_1206#1 61.5,127.4 r180 top
C44 "100uF, X5R, 6.3В, 1206" FOOTPRINT_1206#1 76.4,100.3 r0 bottom
C45 "470uF, 16V, SMD, 10.3 x 10.3" FOOTPRINT_SVPE_F12 298.8,44.7 r90 top
C46 "10 uF, 10%, 25V, X5R, 1206" FOOTPRINT_1206#1 314.4,71.4 r0 top
C47 "10 uF, 10%, 25V, X5R, 1206" FOOTPRINT_1206#1 314.4,73.6 r0 top
C48 "100nF, 10V, X5R, 0402" FOOTPRINT_0402 94.325,51.8 r90 top
C49 "100nF, 10V, X5R, 0402" FOOTPRINT_0402 95.325,51.8 r90 top
C50 "47 пФ, ±5%, NP0, 50В, 0603" FOOTPRINT_0603 53.9,130.7 r0 top
C51 "47 пФ, ±5%, NP0, 50В, 0603" FOOTPRINT_0603 50.8,130.7 r180 top
C52 "10 uF, 10%, 25V, X5R, 1206" FOOTPRINT_1206#1 307.5,61 r0 bottom
C53 "10 uF, 10%, 25V, X5R, 1206" FOOTPRINT_1206#1 307.5,58.7 r0 bottom
C54 "100nF, 10V, X5R, 0402" FOOTPRINT_0402 100.5,46.4 r135 bottom
C55 "100nF, 10V, X5R, 0402" FOOTPRINT_0402 101.2,47.1 r135 bottom
C56 "470uF, 16V, SMD, 10.3 x 10.3" FOOTPRINT_SVPE_F12 298.8,101.8 r90 top
C57 "100nF, 10V, X5R, 0402" FOOTPRINT_0402 56.7,131.7 r270 bottom
C58 "10 uF, 10%, 25V, X5R, 1206" FOOTPRINT_1206#1 314.4,112.5 r0 top
C59 "10 uF, 10%, 25V, X5R, 1206" FOOTPRINT_1206#1 314.4,110.3 r0 top
C60 "100nF, 10V, X5R, 0402" FOOTPRINT_0402 112.059,60.193 r180 top
C61 "100nF, 10V, X5R, 0402" FOOTPRINT_0402 59.1,131.7 r270 bottom
C62 "100nF, 10V, X5R, 0402" FOOTPRINT_0402 112.059,61.183 r180 top
C63 "100nF, 10V, X5R, 0402" FOOTPRINT_0402 57.9,131.7 r270 bottom
C64 "100nF, 10V, X5R, 0402" FOOTPRINT_0402 102.6,50.1 r135 top
C65 "10 uF, 10%, 25V, X5R, 1206" FOOTPRINT_1206#1 307.5,99.9 r0 bottom
C66 "10 uF, 10%, 25V, X5R, 1206" FOOTPRINT_1206#1 307.5,97.6 r0 bottom
C67 "100nF, 10V, X5R, 0402" FOOTPRINT_0402 108.7,59.2 r180 bottom
C68 "100nF, 10V, X5R, 0402" FOOTPRINT_0402 108.7,60.2 r180 bottom
C69 "470uF, 16V, SMD, 10.3 x 10.3" FOOTPRINT_SVPE_F12 298.8,55.6 r90 top
C70 "10 uF, 10%, 25V, X5R, 1206" FOOTPRINT_1206#1 314.4,93 r0 top
C71 "10 uF, 10%, 25V, X5R, 1206" FOOTPRINT_1206#1 314.4,90.8 r0 top
C72 "100nF, 10V, X5R, 0402" FOOTPRINT_0402 107.7,55.9 r180 bottom
C73 "100nF, 10V, X5R, 0402" FOOTPRINT_0402 107.7,56.9 r180 bottom
C74 "10 uF, 10%, 25V, X5R, 1206" FOOTPRINT_1206#1 307.6,80.4 r0 bottom
C75 "10 uF, 10%, 25V, X5R, 1206" FOOTPRINT_1206#1 307.6,78.1 r0 bottom
C76 "100nF, 10V, X5R, 0402" FOOTPRINT_0402 101.9,49.4 r135 top
C77 "100nF, 10V, X5R, 0402" FOOTPRINT_0402 107.8,53.8 r180 top
C78 "470nF, X7R, 16V, 10%, 0603" FOOTPRINT_0603 308.8,81.2 r180 top
C79 "100nF, 10V, X5R, 0402" FOOTPRINT_0402 107.8,54.8 r180 top
C80 "100nF, 10V, X5R, 0402" FOOTPRINT_0402 106.91,71.5 r270 top
C81 "100nF, 10V, X5R, 0402" FOOTPRINT_0402 107.91,71.5 r270 top
C82 "100nF, 10V, X5R, 0402" FOOTPRINT_0402 107.129,68.912 r180 bottom
C83 "470uF, 16V, SMD, 10.3 x 10.3" FOOTPRINT_SVPE_F12 298.8,76 r90 top
C84 "100nF, 10V, X5R, 0402" FOOTPRINT_0402 107.129,69.902 r180 bottom
C85 "470uF, 16V, SMD, 10.3 x 10.3" FOOTPRINT_SVPE_F12 302.5,89.9 r0 bottom
C86 "100nF, 10V, X5R, 0402" FOOTPRINT_0402 97.1,48.2 r135 bottom
C87 "100nF, 10V, X5R, 0402" FOOTPRINT_0402 108.7,61.3 r180 bottom
C88 "100nF, 10V, X5R, 0402" FOOTPRINT_0402 97.8,48.9 r135 bottom
C89 "100nF, 10V, X5R, 0402" FOOTPRINT_0402 108.7,62.3 r180 bottom
C90 "100nF, 10V, X5R, 0402" FOOTPRINT_0402 94.3,47.5 r135 top
C91 "100nF, 10V, X5R, 0402" FOOTPRINT_0402 109.5,61.9 r180 top
C92 "100nF, 10V, X5R, 0402" FOOTPRINT_0402 95,48.2 r135 top
C93 "100nF, 10V, X5R, 0402" FOOTPRINT_0402 109.5,62.9 r180 top
C94 "18pF, 50V, C0G, 0402" FOOTPRINT_0402 119.5,42.6 r90 top
C95 "18pF, 50V, C0G, 0402" FOOTPRINT_0402 113.5,42.4 r45 top
C96 "100nF, 10V, X5R, 0402" FOOTPRINT_0402 67.3,55.8 r270 top
C97 "100nF, 10V, X5R, 0402" FOOTPRINT_0402 112,50.6 r225 bottom
C98 "100nF, 10V, X5R, 0402" FOOTPRINT_0402 112.7,49.9 r225 bottom
C99 "100nF, 10V, X5R, 0402" FOOTPRINT_0402 96.425,35.95 r90 bottom
C100 "100nF, 10V, X5R, 0402" FOOTPRINT_0402 97.575,35.95 r90 bottom
C101 "1.0uF, 10V, X5R, 0402" FOOTPRINT_0402 86.2,61.3 r90 bottom
C102 "1.0uF, 10V, X5R, 0402" FOOTPRINT_0402 99.7,61.7 r90 bottom
C103 "1.0uF, 10V, X5R, 0402" FOOTPRINT_0402 99.8,70.7 r270 bottom
C104 "1.0uF, 10V, X5R, 0402" FOOTPRINT_0402 86.2,70.7 r270 bottom
C105 "100nF, 10V, X5R, 0402" FOOTPRINT_0402 90,61.3 r90 bottom
C106 "100nF, 10V, X5R, 0402" FOOTPRINT_0402 96,61.3 r90 bottom
C107 "100nF, 10V, X5R, 0402" FOOTPRINT_0402 93,61.3 r90 bottom
C108 "10nF, 25V, X7R, 0402" FOOTPRINT_0402 104.8,55.2 r270 bottom
C109 "100nF, 10V, X5R, 0402" FOOTPRINT_0402 88.3,63 r0 bottom
C110 "100nF, 10V, X5R, 0402" FOOTPRINT_0402 97.7,63 r180 bottom
C111 "100nF, 10V, X5R, 0402" FOOTPRINT_0402 88.3,67 r0 bottom
C112 "100nF, 10V, X5R, 0402" FOOTPRINT_0402 97.7,67 r180 bottom
C113 "100nF, 10V, X5R, 0402" FOOTPRINT_0402 96,70.7 r270 bottom
C114 "100nF, 10V, X5R, 0402" FOOTPRINT_0402 93,70.7 r270 bottom
C115 "100nF, 10V, X5R, 0402" FOOTPRINT_0402 90,70.7 r270 bottom
C116 "18pF, 50V, C0G, 0402" FOOTPRINT_0402 72.7,106.6 r90 top
C117 "18pF, 50V, C0G, 0402" FOOTPRINT_0402 72.7,108.7 r270 top
C118 "100nF, 10V, X5R, 0402" FOOTPRINT_0402 70.7,110.5 r90 top
C119 "100nF, 10V, X5R, 0402" FOOTPRINT_0402 70.7,112.5 r90 top
C120 "100pF, 50V, C0G, 0402" FOOTPRINT_0402 74.4,56.725 r90 top
C121 "100uF, X5R, 6.3В, 1206" FOOTPRINT_1206#1 65.8,109.4 r270 bottom
C122 "100nF, 10V, X5R, 0402" FOOTPRINT_0402 58.4,104.3 r0 top
C123 "100nF, 10V, X5R, 0402" FOOTPRINT_0402 65,103.8 r0 top
C124 "100nF, 10V, X5R, 0402" FOOTPRINT_0402 58.6,117 r0 top
C125 "100nF, 10V, X5R, 0402" FOOTPRINT_0402 109.3,54.7 r0 bottom
C126 "100nF, 10V, X5R, 0402" FOOTPRINT_0402 64.5,118.2 r0 top
C127 "10nF, 25V, X7R, 0402" FOOTPRINT_0402 88,61.3 r90 bottom
C128 "10nF, 25V, X7R, 0402" FOOTPRINT_0402 91,61.3 r90 bottom
C129 "10nF, 25V, X7R, 0402" FOOTPRINT_0402 94,61.3 r90 bottom
C130 "10nF, 25V, X7R, 0402" FOOTPRINT_0402 97,61.3 r90 bottom
C131 "10nF, 25V, X7R, 0402" FOOTPRINT_0402 88.3,65 r0 bottom
C132 "10nF, 25V, X7R, 0402" FOOTPRINT_0402 97.7,65 r180 bottom
C133 "10nF, 25V, X7R, 0402" FOOTPRINT_0402 88.3,69 r0 bottom
C134 "10nF, 25V, X7R, 0402" FOOTPRINT_0402 97.7,69 r180 bottom
C135 "10nF, 25V, X7R, 0402" FOOTPRINT_0402 97,70.7 r270 bottom
C136 "10nF, 25V, X7R, 0402" FOOTPRINT_0402 91,70.7 r270 bottom
C137 "10nF, 25V, X7R, 0402" FOOTPRINT_0402 88,70.7 r270 bottom
C138 "10nF, 25V, X7R, 0402" FOOTPRINT_0402 94,70.7 r270 bottom
C139 "1nF, 50V, X7R, 0402" FOOTPRINT_0402 96.5,74.3 r90 bottom
C140 "1nF, 50V, X7R, 0402" FOOTPRINT_0402 88.3,68 r0 bottom
C141 "1nF, 50V, X7R, 0402" FOOTPRINT_0402 88.3,66 r0 bottom
C142 "1nF, 50V, X7R, 0402" FOOTPRINT_0402 89,61.3 r90 bottom
C143 "1nF, 50V, X7R, 0402" FOOTPRINT_0402 98,61.3 r90 bottom
C144 "1nF, 50V, X7R, 0402" FOOTPRINT_0402 92,61.3 r90 bottom
C145 "1nF, 50V, X7R, 0402" FOOTPRINT_0402 88.3,64 r0 bottom
C146 "1nF, 50V, X7R, 0402" FOOTPRINT_0402 97.7,64 r180 bottom
C147 "1nF, 50V, X7R, 0402" FOOTPRINT_0402 97.7,66 r180 bottom
C148 "1nF, 50V, X7R, 0402" FOOTPRINT_0402 97.7,68 r180 bottom
C149 "10 uF, 10%, 25V, X5R, 1206" FOOTPRINT_1206#1 86.8,48.5 r270 top locked
C150 "1nF, 50V, X7R, 0402" FOOTPRINT_0402 98,70.7 r270 bottom
C151 "1nF, 50V, X7R, 0402" FOOTPRINT_0402 95,70.7 r270 bottom
C152 "1nF, 50V, X7R, 0402" FOOTPRINT_0402 95,61.3 r90 bottom
C153 "1nF, 50V, X7R, 0402" FOOTPRINT_0402 92,70.7 r270 bottom
C154 "1nF, 50V, X7R, 0402" FOOTPRINT_0402 89,70.7 r270 bottom
C155 "1nF, 50V, X7R, 0402" FOOTPRINT_0402 106.4,54.7 r180 bottom
C156 "1.0uF, 10V, X5R, 0402" FOOTPRINT_0402 96.7,51.8 r270 top
C157 "1.0uF, 10V, X5R, 0402" FOOTPRINT_0402 84,50.6 r90 bottom
C158 "1.0uF, 10V, X5R, 0402" FOOTPRINT_0402 102.5,73.8 r180 bottom
C159 "1.0uF, 10V, X5R, 0402" FOOTPRINT_0402 85.7,59.8 r180 bottom
C160 "1.0uF, 10V, X5R, 0402" FOOTPRINT_0402 94.8,59.2 r90 bottom
C161 "1.0uF, 10V, X5R, 0402" FOOTPRINT_0402 84,71.3 r90 bottom
C162 "1.0uF, 10V, X5R, 0402" FOOTPRINT_0402 101.9,67.9 r45 bottom
C163 "1.0uF, 10V, X5R, 0402" FOOTPRINT_0402 90,74.3 r90 bottom
C164 "1.0uF, 10V, X5R, 0402" FOOTPRINT_0402 84.3,67.5 r270 bottom
C165 "100nF, 10V, X5R, 0402" FOOTPRINT_0402 98.5,59.7 r180 bottom
C166 "100nF, 10V, X5R, 0402" FOOTPRINT_0402 100.9,64.9 r45 bottom
C167 "100nF, 10V, X5R, 0402" FOOTPRINT_0402 104.2,77.3 r90 bottom
C168 "100nF, 10V, X5R, 0402" FOOTPRINT_0402 85.7,66.5 r90 bottom
C169 "100nF, 10V, X5R, 0402" FOOTPRINT_0402 92,74.3 r90 bottom
C170 "100nF, 10V, X5R, 0402" FOOTPRINT_0402 87.2,74.3 r90 bottom
C171 "10 uF, 10%, 25V, X5R, 1206" FOOTPRINT_1206#1 101.9,76.9 r90 bottom
C172 "10 uF, 10%, 25V, X5R, 1206" FOOTPRINT_1206#1 74.3,67.6 r180 bottom
C173 "100nF, 10V, X5R, 0402" FOOTPRINT_0402 85.6,50.6 r90 bottom
C174 "100nF, 10V, X5R, 0402" FOOTPRINT_0402 86.2,74.3 r90 bottom
C175 "100nF, 10V, X5R, 0402" FOOTPRINT_0402 85.7,68.6 r90 bottom
C176 "100nF, 10V, X5R, 0402" FOOTPRINT_0402 84.3,61.3 r270 bottom
C177 "100nF, 10V, X5R, 0402" FOOTPRINT_0402 88,59.2 r270 bottom
C178 "100nF, 10V, X5R, 0402" FOOTPRINT_0402 93.8,59.2 r270 bottom
C179 "100nF, 10V, X5R, 0402" FOOTPRINT_0402 98.5,74.3 r90 bottom
C180 "10nF, 25V, X7R, 0402" FOOTPRINT_0402 104.9,74.7 r270 bottom
C181 "10nF, 25V, X7R, 0402" FOOTPRINT_0402 90,59.2 r270 bottom
C182 "10nF, 25V, X7R, 0402" FOOTPRINT_0402 99.5,74.3 r90 bottom
C183 "10nF, 25V, X7R, 0402" FOOTPRINT_0402 88.2,74.3 r90 bottom
C184 "10nF, 25V, X7R, 0402" FOOTPRINT_0402 100.2,68.4 r90 bottom
C185 "100nF, 10V, X5R, 0402" FOOTPRINT_0402 107.4,68.325 r180 top
C186 "100nF, 10V, X5R, 0402" FOOTPRINT_0402 107.4,67.325 r180 top
C187 "10nF, 25V, X7R, 0402" FOOTPRINT_0402 85.7,63.5 r90 bottom
C188 "470uF, 16V, SMD, 10.3 x 10.3" FOOTPRINT_SVPE_F12 317.3,107.3 r90 bottom
C189 "10 uF, 10%, 25V, X5R, 1206" FOOTPRINT_1206#1 76.3,53.7 r0 bottom
C190 "470uF, 16V, SMD, 10.3 x 10.3" FOOTPRINT_SVPE_F12 298.8,88.9 r90 top
C191 "100nF, 10V, X5R, 0402" FOOTPRINT_0402 105,68 r180 bottom
C192 "100nF, 10V, X5R, 0402" FOOTPRINT_0402 105,67 r180 bottom
C193 "1nF, 50V, X7R, 0402" FOOTPRINT_0402 86.8,57.8 r90 bottom
C194 "100nF, 10V, X5R, 0402" FOOTPRINT_0402 85.3,52.2 r0 bottom
C195 "1.0uF, 10V, X5R, 0402" FOOTPRINT_0402 85.75,55.8 r270 bottom
C196 "1nF, 50V, X7R, 0402" FOOTPRINT_0402 104.3,59.5 r0 bottom
C197 "1nF, 50V, X7R, 0402" FOOTPRINT_0402 101.2,63.1 r270 bottom
C198 "1nF, 50V, X7R, 0402" FOOTPRINT_0402 87.3,53.5 r270 bottom
C199 "1nF, 50V, X7R, 0402" FOOTPRINT_0402 101.1,59.2 r225 bottom
C200 "1nF, 50V, X7R, 0402" FOOTPRINT_0402 102.3,70.2 r180 bottom
C201 "1nF, 50V, X7R, 0402" FOOTPRINT_0402 104.5,52.6 r270 bottom
C202 "100nF, 10V, X5R, 0402" FOOTPRINT_0402 84.1,53.9 r270 bottom
C203 "1nF, 50V, X7R, 0402" FOOTPRINT_0402 83.7,55.5 r180 bottom
C204 "100nF, 10V, X5R, 0402" FOOTPRINT_0402 104.3,71.7 r0 bottom
C205 "100nF, 10V, X5R, 0402" FOOTPRINT_0402 87.3,52 r270 top
C206 "100nF, 10V, X5R, 0402" FOOTPRINT_0402 103.3,63.8 r180 bottom
C207 "100nF, 10V, X5R, 0402" FOOTPRINT_0402 104.3,60.5 r0 bottom
C208 "100nF, 10V, X5R, 0402" FOOTPRINT_0402 83,50.6 r90 bottom
C209 "100nF, 10V, X5R, 0402" FOOTPRINT_0402 98.5,55.7 r270 bottom
C210 "100nF, 10V, X5R, 0402" FOOTPRINT_0402 100.7,55.3 r180 bottom
C211 "1nF, 50V, X7R, 0402" FOOTPRINT_0402 101.7,54.2 r180 bottom
C212 "100nF, 10V, X5R, 0402" FOOTPRINT_0402 102.5,52.6 r270 bottom
C213 "1.0uF, 10V, X5R, 0402" FOOTPRINT_0402 104.3,72.7 r0 bottom
C214 "1.0uF, 10V, X5R, 0402" FOOTPRINT_0402 86.3,52 r270 top
C215 "1.0uF, 10V, X5R, 0402" FOOTPRINT_0402 106.2,65 r0 bottom
C216 "1.0uF, 10V, X5R, 0402" FOOTPRINT_0402 100.7,56.3 r180 bottom
C217 "100nF, 10V, X5R, 0402" FOOTPRINT_0402 105.9,71.5 r90 bottom
C218 "100nF, 10V, X5R, 0402" FOOTPRINT_0402 107.3,63.3 r0 top
C219 "100nF, 10V, X5R, 0402" FOOTPRINT_0402 96.3,55.7 r90 bottom
C220 "100nF, 10V, X5R, 0402" FOOTPRINT_0402 91,52 r270 top
C221 "1.0uF, 10V, X5R, 0402" FOOTPRINT_0402 56,47.5 r180 top
C222 "100nF, 10V, X5R, 0402" FOOTPRINT_0402 103.5,52.6 r270 bottom
C223 "100nF, 10V, X5R, 0402" FOOTPRINT_0402 125.9,42.5 r0 top
C224 "1nF, 50V, X7R, 0402" FOOTPRINT_0402 106.9,71.5 r90 bottom
C225 "1nF, 50V, X7R, 0402" FOOTPRINT_0402 91.6,54.8 r270 bottom
C226 "1nF, 50V, X7R, 0402" FOOTPRINT_0402 107.3,63.4 r0 bottom
C227 "100nF, 10V, X5R, 0402" FOOTPRINT_0402 58,40 r180 bottom
C228 "1nF, 50V, X7R, 0402" FOOTPRINT_0402 85.2,74.3 r90 bottom
C229 "1nF, 50V, X7R, 0402" FOOTPRINT_0402 84.3,63.5 r90 bottom
C230 "1nF, 50V, X7R, 0402" FOOTPRINT_0402 97.5,74.3 r90 bottom
C231 "1nF, 50V, X7R, 0402" FOOTPRINT_0402 105.8,77.3 r90 bottom
C232 "1nF, 50V, X7R, 0402" FOOTPRINT_0402 99.9,65.9 r45 bottom
C233 "1nF, 50V, X7R, 0402" FOOTPRINT_0402 100.8,60.7 r45 bottom
C234 "1nF, 50V, X7R, 0402" FOOTPRINT_0402 92,59.2 r270 bottom
C235 "1nF, 50V, X7R, 0402" FOOTPRINT_0402 84.3,65.5 r270 bottom
C236 "1nF, 50V, X7R, 0402" FOOTPRINT_0402 85,71.3 r90 bottom
C237 "1nF, 50V, X7R, 0402" FOOTPRINT_0402 82.2,54.7 r90 bottom
C238 "100nF, 10V, X5R, 0402" FOOTPRINT_0402 82.2,52.7 r270 bottom
C239 "100uF, X5R, 6.3В, 1206" FOOTPRINT_1206#1 56,51.2 r270 top
D1 "LMZ22005" LMZ22005TZ 320.2,47 r270 top
D2 "LMZ22005" LMZ22005TZ 320.2,64.8 r270 top
D3 "LMZ22005" LMZ22005TZ 320.2,103.7 r270 top
D4 "LMZ22005" LMZ22005TZ 320.2,84.2 r270 top
D5 "SN74LVT125DR" SOIC-14 88.8,111.4 r180 bottom
D6 "SN74LVT125DR" SOIC-14 145.5,111.4 r0 bottom
D7 "SN74LVT125DR" SOIC-14 202.7,111.4 r0 bottom
D8 "SN74LVT125DR" SOIC-14 259.6,111.4 r0 bottom
D9 "1923KX028" FOOTPRINT_MK8303.576-1 93,66 r0 top locked
D10 "TMP421, SOT-23" SOT-23 71.1,55.35 r90 top locked
D11 "1986BE92Q" LQFP64 63.5,111 r0 top locked
D12 "FT230XS" SSOP-16 58.9,126.4 r180 bottom
D13 "1636RR3U" FOOTPRINT_H14.42-1B 57,51.5 r90 bottom
D14 "SN74HC595" SOIC-16 116,111.4 r0 top
D15 "SN74HC595" SOIC-16 230,111.4 r180 bottom
D16 "TCA9546ADR" SOIC-16 88.8,110.1 r270 top
G1 "25.0 MHz, +3.3V" FOOTPRINT_KX7 122.9,43.3 r180 top locked
L1 "0805" FOOTPRINT_0805 79.9,52.9 r90 bottom
L2 "0805" FOOTPRINT_0805 79.8,56.9 r0 bottom
L3 "0805" FOOTPRINT_0805 80.5,47.5 r270 top
L4 "0805" FOOTPRINT_0805 72.3,111.7 r270 top
L5 "0805" FOOTPRINT_0805 83.7,46.7 r0 top
L6 "0805" FOOTPRINT_0805 65.4,122.2 r270 top
R1 "4.02K 1% 0805" FOOTPRINT_0805 308.3,109.7 r90 bottom
R2 "280 1% 0402" FOOTPRINT_0402 301.8,45.1 r270 bottom
R3 "280 1% 0402" FOOTPRINT_0402 303.1,45.1 r270 bottom
R4 "680, 5%, 0603" FOOTPRINT_0603 307.5,102.8 r270 bottom
R5 "680, 5%, 0603" FOOTPRINT_0603 305.8,102.8 r270 bottom
R6 "11K, 1%, 0402" FOOTPRINT_0402 72.5,115.5 r180 bottom
R7 "24, 1%, 0402" FOOTPRINT_0402 52.9,128.8 r90 top
R8 "24, 1%, 0402" FOOTPRINT_0402 51.8,128.8 r90 top
R9 "11K, 1%, 0402" FOOTPRINT_0402 60.6,121.1 r270 bottom
R10 "11K, 1%, 0402" FOOTPRINT_0402 59.1,121.1 r270 bottom
R11 "280 1% 0402" FOOTPRINT_0402 47.2,125 r0 top
R12 "280 1% 0402" FOOTPRINT_0402 44.9,125 r0 top
R13 "11K, 1%, 0402" FOOTPRINT_0402 80.2,87.6 r90 top
R14 "2.49K, 1%, 0402" FOOTPRINT_0402 163.1,100.3 r270 bottom
R15 "11K, 1%, 0402" FOOTPRINT_0402 78,87.6 r90 top
R16 "2.49K, 1%, 0402" FOOTPRINT_0402 162,100.3 r270 bottom
R17 "11K, 1%, 0402" FOOTPRINT_0402 141.5,88 r0 top
R18 "11K, 1%, 0402" FOOTPRINT_0402 143.6,88 r180 top
R19 "11K, 1%, 0402" FOOTPRINT_0402 143,104.7 r270 bottom
R20 "11K, 1%, 0402" FOOTPRINT_0402 143,102.6 r90 bottom
R21 "2.49K, 1%, 0402" FOOTPRINT_0402 141.5,89.1 r180 top
R22 "2.49K, 1%, 0402" FOOTPRINT_0402 143.6,89.1 r0 top
R23 "2.49K, 1%, 0402" FOOTPRINT_0402 144.1,104.7 r90 bottom
R24 "2.49K, 1%, 0402" FOOTPRINT_0402 144.1,102.6 r270 bottom
R25 "11K, 1%, 0402" FOOTPRINT_0402 143.6,100.9 r180 bottom
R26 "11K, 1%, 0402" FOOTPRINT_0402 141.5,100.9 r0 bottom
R27 "6.04K, 1%, 0402" FOOTPRINT_0402 90.5,100.9 r0 top
R28 "6.04K, 1%, 0402" FOOTPRINT_0402 92.6,100.9 r180 top
R29 "6.04K, 1%, 0402" FOOTPRINT_0402 147.5,100.9 r0 top
R30 "4.02K 1% 0805" FOOTPRINT_0805 307.5,70.3 r180 bottom
R31 "49.9, 1%, 0402" FOOTPRINT_0402 300,66.6 r0 top
R32 "6.04K, 1%, 0402" FOOTPRINT_0402 149.6,100.9 r180 top
R33 "280 1% 0402" FOOTPRINT_0402 300,67.9 r180 top
R34 "4.02K 1% 0805" FOOTPRINT_0805 307.5,72.5 r180 bottom
R35 "2.49K, 1%, 0402" FOOTPRINT_0402 143.6,99.8 r0 bottom
R36 "523, 1%, 0603" FOOTPRINT_0603 308.8,49.9 r0 top
R37 "33.2K 1% 0603" FOOTPRINT_0603 307.5,63.8 r90 bottom
R38 "2.49K, 1%, 0402" FOOTPRINT_0402 141.5,99.8 r180 bottom
R39 "2.49K, 1%, 0402" FOOTPRINT_0402 90.5,99.8 r180 top
R40 "470, 1%, 0603" FOOTPRINT_0603 308.8,48.3 r180 top
R41 "2K, 1%, 0603" FOOTPRINT_0603 308.7,45.7 r180 bottom
R42 "2.49K, 1%, 0402" FOOTPRINT_0402 92.6,99.8 r0 top
R43 "523, 1%, 0603" FOOTPRINT_0603 308.8,67.8 r0 top
R44 "5.23K, 1%, 0603" FOOTPRINT_0603 308.8,45.7 r180 top
R45 "2.49K, 1%, 0402" FOOTPRINT_0402 147.5,99.8 r180 top
R46 "470, 1%, 0603" FOOTPRINT_0603 308.8,66.1 r180 top
R47 "2K, 1%, 0603" FOOTPRINT_0603 309.2,63.8 r270 bottom
R48 "2.49K, 1%, 0402" FOOTPRINT_0402 149.6,99.8 r0 top
R49 "35.7K, 1%, 0603" FOOTPRINT_0603 308.8,106.8 r0 top
R50 "5.23K, 1%, 0603" FOOTPRINT_0603 308.8,63.5 r180 top
R51 "11K, 1%, 0402" FOOTPRINT_0402 161.52,89.1 r0 top locked
R52 "5.23K, 1%, 0603" FOOTPRINT_0603 308.8,105.1 r180 top
R53 "5.23K, 1%, 0603" FOOTPRINT_0603 309.2,102.8 r270 bottom
R54 "1.65K, 1%, 0603" FOOTPRINT_0603 308.8,102.3 r180 top
R55 "35.7K, 1%, 0603" FOOTPRINT_0603 308.8,87.2 r0 top
R56 "5.23K, 1%, 0603" FOOTPRINT_0603 308.8,85.5 r180 top
R57 "5.23K, 1%, 0603" FOOTPRINT_0603 308.7,82.9 r180 bottom
R58 "1.65K, 1%, 0603" FOOTPRINT_0603 308.8,82.9 r180 top
R59 "11K, 1%, 0402" FOOTPRINT_0402 163.62,89.1 r180 top locked
R60 "11K, 1%, 0402" FOOTPRINT_0402 125.9,88.1 r0 bottom
R61 "11K, 1%, 0402" FOOTPRINT_0402 128,88.1 r180 bottom
R62 "2.49K, 1%, 0402" FOOTPRINT_0402 161.52,88 r180 top locked
R63 "2.49K, 1%, 0402" FOOTPRINT_0402 163.62,88 r0 top locked
R64 "2.49K, 1%, 0402" FOOTPRINT_0402 125.9,87 r180 bottom
R65 "2.49K, 1%, 0402" FOOTPRINT_0402 128,87 r0 bottom
R66 "2.49K, 1%, 0402" FOOTPRINT_0402 220.1,100.3 r270 bottom
R67 "2.49K, 1%, 0402" FOOTPRINT_0402 219,100.3 r270 bottom
R68 "11K, 1%, 0402" FOOTPRINT_0402 255.5,89.1 r0 top
R69 "11K, 1%, 0402" FOOTPRINT_0402 257.6,89.1 r180 top
R70 "2.49K, 1%, 0402" FOOTPRINT_0402 255.5,88 r180 top
R71 "2.49K, 1%, 0402" FOOTPRINT_0402 257.6,88 r0 top
R72 "6.04K, 1%, 0402" FOOTPRINT_0402 204.5,100.9 r0 top
R73 "6.04K, 1%, 0402" FOOTPRINT_0402 206.6,100.9 r180 top
R74 "11K, 1%, 0402" FOOTPRINT_0402 200.6,100.9 r180 bottom
R75 "11K, 1%, 0402" FOOTPRINT_0402 198.5,100.9 r0 bottom
R76 "6.04K, 1%, 0402" FOOTPRINT_0402 261.5,100.9 r0 top
R77 "6.04K, 1%, 0402" FOOTPRINT_0402 263.6,100.9 r180 top
R78 "2.49K, 1%, 0402" FOOTPRINT_0402 204.5,99.8 r180 top
R79 "2.49K, 1%, 0402" FOOTPRINT_0402 206.6,99.8 r0 top
R80 "2.49K, 1%, 0402" FOOTPRINT_0402 200.6,99.8 r0 bottom
R81 "2.49K, 1%, 0402" FOOTPRINT_0402 198.5,99.8 r180 bottom
R82 "2.49K, 1%, 0402" FOOTPRINT_0402 261.5,99.8 r180 top
R83 "2.49K, 1%, 0402" FOOTPRINT_0402 263.6,99.8 r0 top
R84 "11K, 1%, 0402" FOOTPRINT_0402 275.5,89.1 r0 top
R85 "11K, 1%, 0402" FOOTPRINT_0402 277.6,89.1 r180 top
R86 "2.49K, 1%, 0402" FOOTPRINT_0402 275.5,88 r180 top
R87 "2.49K, 1%, 0402" FOOTPRINT_0402 277.6,88 r0 top
R88 "2.49K, 1%, 0402" FOOTPRINT_0402 277.1,100.3 r270 bottom
R89 "2.49K, 1%, 0402" FOOTPRINT_0402 276,100.3 r270 bottom
R90 "2.49K, 1%, 0402" FOOTPRINT_0402 106.1,100.3 r270 bottom
R91 "2.49K, 1%, 0402" FOOTPRINT_0402 105,100.3 r270 bottom
R92 "11K, 1%, 0402" FOOTPRINT_0402 260.6,88.1 r0 bottom
R93 "11K, 1%, 0402" FOOTPRINT_0402 262.7,88.1 r180 bottom
R94 "11K, 1%, 0402" FOOTPRINT_0402 148,106.6 r90 bottom
R95 "11K, 1%, 0402" FOOTPRINT_0402 262.1,106.4 r90 bottom
R96 "2.49K, 1%, 0402" FOOTPRINT_0402 260.6,87 r180 bottom
R97 "2.49K, 1%, 0402" FOOTPRINT_0402 262.7,87 r0 bottom
R98 "11K, 1%, 0402" FOOTPRINT_0402 257.6,100.9 r180 bottom
R99 "11K, 1%, 0402" FOOTPRINT_0402 255.5,100.9 r0 bottom
R100 "1.82K, 1%, 0402" FOOTPRINT_0402 154.6,88.5 r90 top
R101 "11K, 1%, 0402" FOOTPRINT_0402 86.6,100.9 r180 bottom
R102 "24, 1%, 0402" FOOTPRINT_0402 120.5,42.6 r270 top
R103 "11K, 1%, 0402" FOOTPRINT_0402 84.5,100.9 r0 bottom
R104 "1.82K, 1%, 0402" FOOTPRINT_0402 267.3,88.6 r90 bottom
R105 "2.49K, 1%, 0402" FOOTPRINT_0402 257.6,99.8 r0 bottom
R106 "2.49K, 1%, 0402" FOOTPRINT_0402 255.5,99.8 r180 bottom
R107 "2.49K, 1%, 0402" FOOTPRINT_0402 86.6,99.8 r0 bottom
R108 "2.49K, 1%, 0402" FOOTPRINT_0402 84.5,99.8 r180 bottom
R109 "11K, 1%, 0402" FOOTPRINT_0402 70.8,56.3 r180 bottom
R110 "11K, 1%, 0402" FOOTPRINT_0402 70.8,57.3 r180 bottom
R111 "24, 1%, 0402" FOOTPRINT_0402 73.8,61 r180 top
R112 "11K, 1%, 0402" FOOTPRINT_0402 239.4,87 r0 bottom
R113 "11K, 1%, 0402" FOOTPRINT_0402 241.5,87 r180 bottom
R114 "2.49K, 1%, 0402" FOOTPRINT_0402 239.4,88.1 r180 bottom
R115 "2.49K, 1%, 0402" FOOTPRINT_0402 241.5,88.1 r0 bottom
R116 "11K, 1%, 0402" FOOTPRINT_0402 115.3,114.1 r270 bottom
R117 "11K, 1%, 0402" FOOTPRINT_0402 119.2,114.1 r270 bottom
R118 "11K, 1%, 0402" FOOTPRINT_0402 114,114.1 r90 bottom
R119 "11K, 1%, 0402" FOOTPRINT_0402 116.6,114.1 r90 bottom
R120 "11K, 1%, 0402" FOOTPRINT_0402 117.9,114.1 r90 bottom
R121 "2.49K, 1%, 0402" FOOTPRINT_0402 128.9,100.3 r90 top
R122 "2.49K, 1%, 0402" FOOTPRINT_0402 160.9,100.3 r90 bottom
R123 "2.49K, 1%, 0402" FOOTPRINT_0402 130,100.3 r90 top
R124 "2.49K, 1%, 0402" FOOTPRINT_0402 159.8,100.3 r90 bottom
R125 "2.49K, 1%, 0402" FOOTPRINT_0402 132.2,100.3 r90 top
R126 "2.49K, 1%, 0402" FOOTPRINT_0402 158.7,100.3 r90 bottom
R127 "2.49K, 1%, 0402" FOOTPRINT_0402 157.6,100.3 r90 bottom
R128 "2.49K, 1%, 0402" FOOTPRINT_0402 72.4,100.3 r90 top
R129 "2.49K, 1%, 0402" FOOTPRINT_0402 73.5,100.3 r90 top
R130 "2.49K, 1%, 0402" FOOTPRINT_0402 74.6,100.3 r90 top
R131 "2.49K, 1%, 0402" FOOTPRINT_0402 131.1,100.3 r90 top
R132 "2.49K, 1%, 0402" FOOTPRINT_0402 75.7,100.3 r90 top
R133 "2.49K, 1%, 0402" FOOTPRINT_0402 94.2,100.3 r90 top
R134 "11K, 1%, 0402" FOOTPRINT_0402 52.5,63.6 r90 bottom
R135 "11K, 1%, 0402" FOOTPRINT_0402 52,40 r180 bottom
R136 "11K, 1%, 0402" FOOTPRINT_0402 69,50.7 r270 bottom
R137 "11K, 1%, 0402" FOOTPRINT_0402 62,40 r0 bottom
R138 "49.9, 1%, 0402" FOOTPRINT_0402 75.9,56.225 r0 top
R139 "49.9, 1%, 0402" FOOTPRINT_0402 75.9,57.225 r0 top
R140 "280 1% 0402" FOOTPRINT_0402 69.8,52.6 r180 top
R141 "11K, 1%, 0402" FOOTPRINT_0402 58.6,50.4 r90 top
R142 "11K, 1%, 0402" FOOTPRINT_0402 57.9,67.3 r270 bottom
R143 "280 1% 0402" FOOTPRINT_0402 69.8,51.6 r180 top
R144 "11K, 1%, 0402" FOOTPRINT_0402 84,51 r270 top
R145 "280 1% 0402" FOOTPRINT_0402 69.8,50.6 r180 top
R146 "2.49K, 1%, 0402" FOOTPRINT_0402 96.4,100.3 r90 top
R147 "2.49K, 1%, 0402" FOOTPRINT_0402 95.3,100.3 r90 top
R148 "2.49K, 1%, 0402" FOOTPRINT_0402 97.5,100.3 r90 top
R149 "2.49K, 1%, 0402" FOOTPRINT_0402 151.2,100.3 r90 top
R150 "2.49K, 1%, 0402" FOOTPRINT_0402 139.9,100.3 r90 bottom
R151 "2.49K, 1%, 0402" FOOTPRINT_0402 154.5,100.3 r90 top
R152 "11K, 1%, 0402" FOOTPRINT_0402 72.5,116.6 r180 bottom
R153 "11K, 1%, 0402" FOOTPRINT_0402 60,67.3 r270 bottom
R154 "2.49K, 1%, 0402" FOOTPRINT_0402 137.7,100.3 r90 bottom
R155 "2.49K, 1%, 0402" FOOTPRINT_0402 138.8,100.3 r90 bottom
R156 "2.49K, 1%, 0402" FOOTPRINT_0402 152.3,100.3 r90 top
R157 "2.49K, 1%, 0402" FOOTPRINT_0402 136.6,100.3 r90 bottom
R158 "2.49K, 1%, 0402" FOOTPRINT_0402 153.4,100.3 r90 top
R159 "2.49K, 1%, 0402" FOOTPRINT_0402 186.1,100.3 r90 top
R160 "2K, 1%, 0603" FOOTPRINT_0603 59,69.9 r0 bottom
R161 "11K, 1%, 0402" FOOTPRINT_0402 56.8,84 r90 bottom
R162 "280 1% 0402" FOOTPRINT_0402 82,51 r270 top
R163 "280 1% 0402" FOOTPRINT_0402 83,51 r270 top
R164 "11K, 1%, 0402" FOOTPRINT_0402 54.6,84 r90 bottom
R165 "11K, 1%, 0402" FOOTPRINT_0402 57.9,84 r90 bottom
R166 "200, 1%, 0402" FOOTPRINT_0402 111,54.1 r45 bottom
R167 "11K, 1%, 0402" FOOTPRINT_0402 55.7,84 r90 bottom
R168 "200, 1%, 0402" FOOTPRINT_0402 84.8,58.2 r180 bottom
R169 "4 x 10K, 5%, 0804" FOOTPRINT_0804_RES_ARRAY 59.2,75.225 r0 top locked
R170 "4 x 10K, 5%, 0804" FOOTPRINT_0804_RES_ARRAY 130.8,75.5 r90 top
R171 "11K, 1%, 0402" FOOTPRINT_0402 67.6,104.9 r90 bottom
R172 "4 x 10K, 5%, 0804" FOOTPRINT_0804_RES_ARRAY 65.3,63.5 r180 bottom
R173 "11K, 1%, 0402" FOOTPRINT_0402 68.8,104.9 r90 bottom
R174 "4 x 10K, 5%, 0804" FOOTPRINT_0804_RES_ARRAY 52,110.5 r0 bottom
R175 "11K, 1%, 0402" FOOTPRINT_0402 61.2,101.9 r180 bottom
R176 "11K, 1%, 0402" FOOTPRINT_0402 67.8,57 r180 bottom
R177 "11K, 1%, 0402" FOOTPRINT_0402 67.8,58.1 r180 bottom
R178 "4 x 10K, 5%, 0804" FOOTPRINT_0804_RES_ARRAY 37.3,106.6 r270 top locked
R179 "4 x 10K, 5%, 0804" FOOTPRINT_0804_RES_ARRAY 50.8,123.1 r90 bottom
R180 "11K, 1%, 0402" FOOTPRINT_0402 127.4,44.6 r90 top
R181 "11K, 1%, 0402" FOOTPRINT_0402 106.7,75.2 r270 bottom
R182 "11K, 1%, 0402" FOOTPRINT_0402 79.1,87.6 r90 top
R183 "11K, 1%, 0402" FOOTPRINT_0402 100.2,87.2 r90 top
R184 "11K, 1%, 0402" FOOTPRINT_0402 98,87.2 r90 top
R185 "11K, 1%, 0402" FOOTPRINT_0402 99.1,87.2 r90 top
R186 "2.49K, 1%, 0402" FOOTPRINT_0402 217.9,100.3 r90 bottom
R187 "2.49K, 1%, 0402" FOOTPRINT_0402 242.9,100.3 r90 top
R188 "2.49K, 1%, 0402" FOOTPRINT_0402 187.2,100.3 r90 top
R189 "2.49K, 1%, 0402" FOOTPRINT_0402 216.8,100.3 r90 bottom
R190 "2.49K, 1%, 0402" FOOTPRINT_0402 244,100.3 r90 top
R191 "2.49K, 1%, 0402" FOOTPRINT_0402 188.3,100.3 r90 top
R192 "2.49K, 1%, 0402" FOOTPRINT_0402 215.7,100.3 r90 bottom
R193 "2.49K, 1%, 0402" FOOTPRINT_0402 246.2,100.3 r90 top
R194 "2.49K, 1%, 0402" FOOTPRINT_0402 189.4,100.3 r90 top
R195 "2.49K, 1%, 0402" FOOTPRINT_0402 214.6,100.3 r90 bottom
R196 "2.49K, 1%, 0402" FOOTPRINT_0402 245.1,100.3 r90 top
R197 "2.49K, 1%, 0402" FOOTPRINT_0402 208.2,100.3 r90 top
R198 "2.49K, 1%, 0402" FOOTPRINT_0402 210.4,100.3 r90 top
R199 "2.49K, 1%, 0402" FOOTPRINT_0402 196.9,100.3 r90 bottom
R200 "2.49K, 1%, 0402" FOOTPRINT_0402 265.2,100.3 r90 top
R201 "2.49K, 1%, 0402" FOOTPRINT_0402 211.5,100.3 r90 top
R202 "2.49K, 1%, 0402" FOOTPRINT_0402 195.8,100.3 r90 bottom
R203 "2.49K, 1%, 0402" FOOTPRINT_0402 268.5,100.3 r90 top
R204 "2.49K, 1%, 0402" FOOTPRINT_0402 209.3,100.3 r90 top
R205 "2.49K, 1%, 0402" FOOTPRINT_0402 194.7,100.3 r90 bottom
R206 "2.49K, 1%, 0402" FOOTPRINT_0402 266.3,100.3 r90 top
R207 "2.49K, 1%, 0402" FOOTPRINT_0402 193.6,100.3 r90 bottom
R208 "2.49K, 1%, 0402" FOOTPRINT_0402 267.4,100.3 r90 top
R209 "2.49K, 1%, 0402" FOOTPRINT_0402 274.9,100.3 r90 bottom
R210 "2.49K, 1%, 0402" FOOTPRINT_0402 103.9,100.3 r90 bottom
R211 "2.49K, 1%, 0402" FOOTPRINT_0402 273.8,100.3 r90 bottom
R212 "2.49K, 1%, 0402" FOOTPRINT_0402 102.8,100.3 r90 bottom
R213 "2.49K, 1%, 0402" FOOTPRINT_0402 272.7,100.3 r90 bottom
R214 "2.49K, 1%, 0402" FOOTPRINT_0402 101.7,100.3 r90 bottom
R215 "2.49K, 1%, 0402" FOOTPRINT_0402 271.6,100.3 r90 bottom
R216 "2.49K, 1%, 0402" FOOTPRINT_0402 100.6,100.3 r90 bottom
R217 "2.49K, 1%, 0402" FOOTPRINT_0402 253.9,100.3 r90 bottom
R218 "2.49K, 1%, 0402" FOOTPRINT_0402 82.9,100.3 r90 bottom
R219 "2.49K, 1%, 0402" FOOTPRINT_0402 251.7,100.3 r90 bottom
R220 "2.49K, 1%, 0402" FOOTPRINT_0402 81.8,100.3 r90 bottom
R221 "2.49K, 1%, 0402" FOOTPRINT_0402 252.8,100.3 r90 bottom
R222 "2.49K, 1%, 0402" FOOTPRINT_0402 80.7,100.3 r90 bottom
R223 "2.49K, 1%, 0402" FOOTPRINT_0402 250.6,100.3 r90 bottom
R224 "2.49K, 1%, 0402" FOOTPRINT_0402 79.6,100.3 r90 bottom
R225 "24, 1%, 0402" FOOTPRINT_0402 76.1,60.25 r180 top
R226 "24, 1%, 0402" FOOTPRINT_0402 73.8,59.5 r180 top
R227 "24, 1%, 0402" FOOTPRINT_0402 76.1,58.8 r180 top
R228 "11K, 1%, 0402" FOOTPRINT_0402 98,87.2 r90 bottom
R229 "11K, 1%, 0402" FOOTPRINT_0402 99.1,87.2 r90 bottom
R230 "11K, 1%, 0402" FOOTPRINT_0402 100.2,87.2 r90 bottom
R231 "11K, 1%, 0402" FOOTPRINT_0402 77.3,87.6 r90 bottom
R232 "11K, 1%, 0402" FOOTPRINT_0402 78.4,87.6 r90 bottom
R233 "11K, 1%, 0402" FOOTPRINT_0402 79.5,87.6 r90 bottom
R234 "11K, 1%, 0402" FOOTPRINT_0402 83.1,112 r0 top
SA1 "R19A-12BBBT-G" pwr_switch 301,129.4 r90 top locked
SA2 "DMHA-04G-G" FOOTPRINT_DMHA-04G-G 65.8,68.7 r0 top locked
SA3 "DMHA-04G-G" FOOTPRINT_DMHA-04G-G 127.4,71.9 r90 bottom
SA4 "DMHA-04G-G" FOOTPRINT_DMHA-04G-G 119.4,49.2 r0 bottom locked
SA5 "DMHA-04G-G" FOOTPRINT_DMHA-04G-G 58.4,76.5 r0 bottom locked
